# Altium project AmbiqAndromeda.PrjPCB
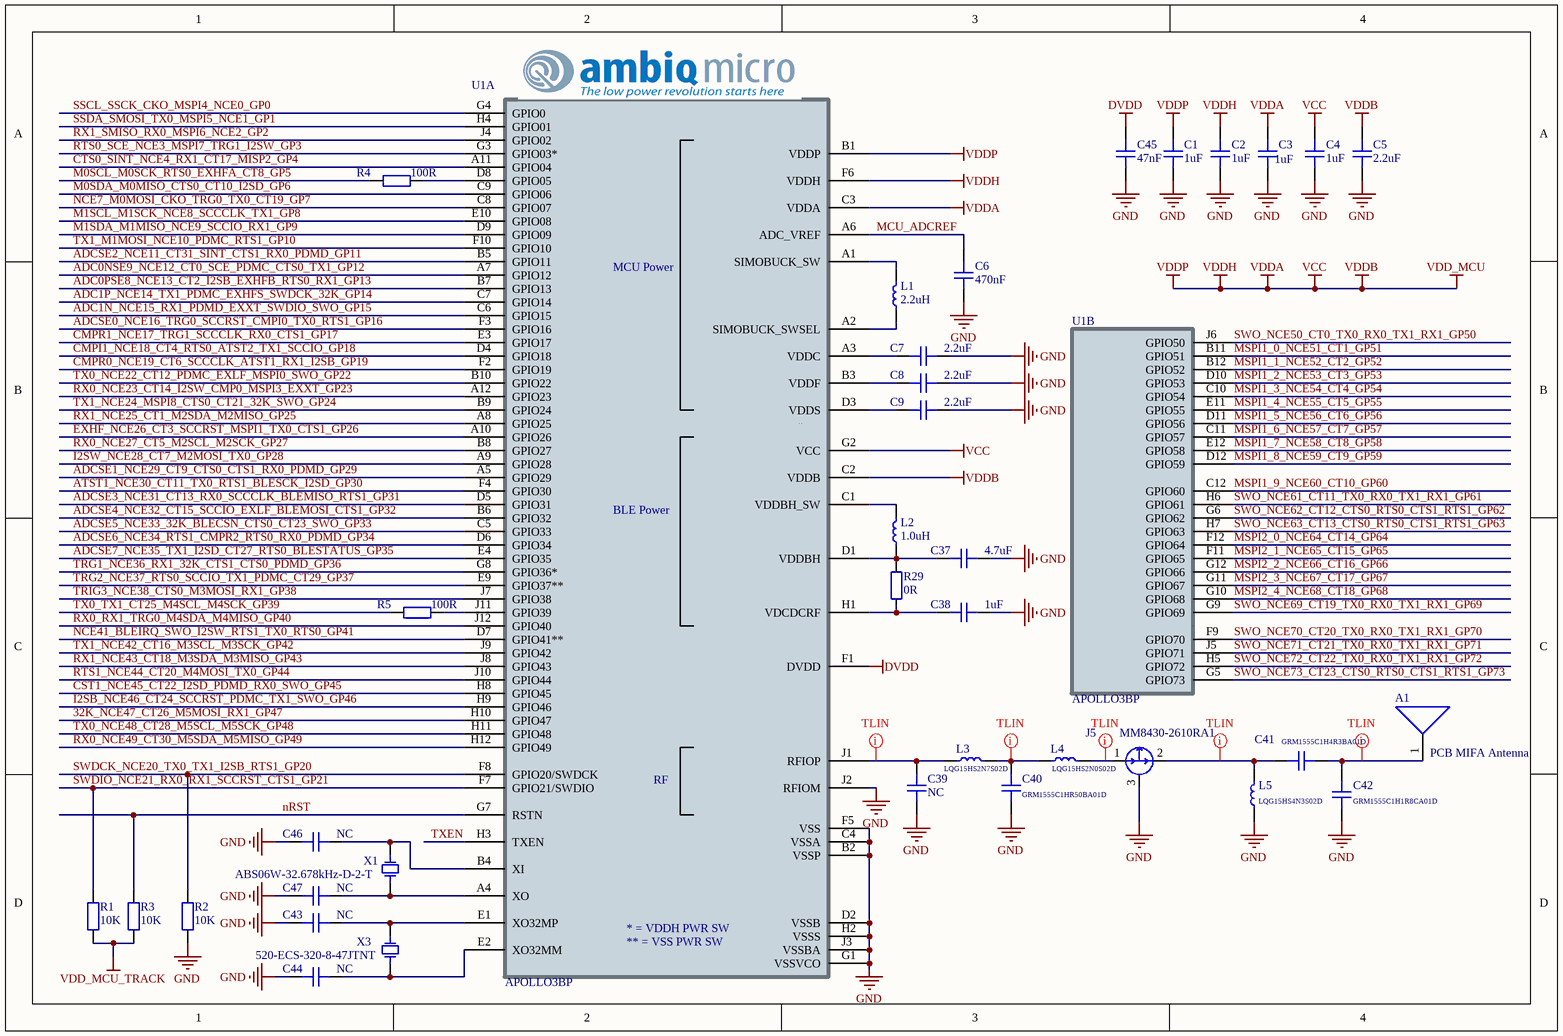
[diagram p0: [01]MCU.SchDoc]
10 sheets, 255 parts. Net scope: global (net labels, ports and power ports of the same name join across sheets).
Board file: AmbiqAndromeda.PcbDoc
Sheets:
  [01]MCU.SchDoc
  [02]Arduino Headers.SchDoc
  [03]Breakout Headers.SchDoc
  [04]Power Supplies.SchDoc
  [05]Power Supply Tracker.SchDoc
  [06]J-Link OB Debugger.SchDoc
  [07]User Interface.SchDoc
  [08]Debug Headers and Support.SchDoc
  [09]USBHub.SchDoc
  [10]USBSPIBridge.SchDoc

## Sheet [01]MCU.SchDoc
size A4; Organization: Altium Limited; Address1: L3, 12a Rodborough Rd; Address2: Frenchs Forest; Address3: NSW; Address4: Australia 2086

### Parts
A1  PCB MIFA Antenna  [MIFA_AMBIQ]  (net tie, no BOM)
C1  1uF  [CAPC0603L]
C2  1uF  [CAPC0603L]
C3  1uF  [CAPC0603L]
C4  1uF  [CAPC0603L]
C5  2.2uF  [CAPC0603L]
C6  470nF  [CAPC0603L]
C7  2.2uF  [CAPC0603L]
C8  2.2uF  [CAPC0603L]
C9  2.2uF  [CAPC0603L]
C37  4.7uF  [CAPC0603L]
C38  1uF  [CAPC0603L]
C39  NC  [CAPC1005L]
C40  GRM1555C1HR50BA01D  [CAPC1005L]
C41  GRM1555C1H4R3BA01D  [CAPC1005L]
C42  GRM1555C1H1R8CA01D  [CAPC1005L]
C43  NC  [CAPC0603L]
C44  NC  [CAPC0603L]
C45  47nF  [CAPC0603L]
C46  NC  [CAPC0603L]
C47  NC  [CAPC0603L]
J5  MM8430-2610RA1  [MM8430-2610RA1]
L1  2.2uH  [BRC2012]
L2  1.0uH  [DFE18SAN]
L3  LQG15HS2N7S02D  [INDC1005L]
L4  LQG15HS2N0S02D  [INDC1005L]
L5  LQG15HS4N3S02D  [INDC1005L]
R1  10K  [RESC1005L]
R2  10K  [RESC1005L]
R3  10K  [RESC1005L]
R4  100R  [RESC1005L]
R5  100R  [RESC1005L]
R29  0R  [RESC0603L]
U1  APOLLO3BP  [BGA104C40P12X9_530X430X80L]  (parts A,B of 2)
X1  ABS06W-32.678kHz-D-2-T  [ABS06W]
X3  520-ECS-320-8-47JTNT  [ECX-1247]

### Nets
DVDD: C45.2 U1.F1(DVDD)
GND: C1.1 C2.1 C3.1 C4.1 C5.1 C6.1 C7.1 C8.1 C9.1 C37.1 C38.1 C39.2 C40.2 C42.2 C43.2 C44.2 C45.1 C46.2 C47.2 J5.3 L5.1 R2.1 U1.B2(VSSP) U1.C4(VSSA) U1.D2(VSSB) U1.F5(VSS) U1.G1(VSSVCO) U1.H2(VSSS) U1.J2(RFIOM) U1.J3(VSSBA) X3.2(GND) X3.4(GND)
VDD_MCU: C1.2 C2.2 C3.2 C4.2 C5.2 U1.B1(VDDP) U1.C2(VDDB) U1.C3(VDDA) U1.F6(VDDH) U1.G2(VCC)  [also labelled VCC, VDDA, VDDB, VDDH, VDDP]
VDD_MCU_TRACK: R1.1 R3.1
32K_NCE47_CT26_M5MOSI_RX1_GP47: U1.H10(GPIO47)
ADC0NSE9_NCE12_CT0_SCE_PDMC_CTS0_TX1_GP12: U1.A7(GPIO12)
ADC0PSE8_NCE13_CT2_I2SB_EXHFB_RTS0_RX1_GP13: U1.B7(GPIO13)
ADC1N_NCE15_RX1_PDMD_EXXT_SWDIO_SWO_GP15: U1.C6(GPIO15)
ADC1P_NCE14_TX1_PDMC_EXHFS_SWDCK_32K_GP14: U1.C7(GPIO14)
ADCSE0_NCE16_TRG0_SCCRST_CMPI0_TX0_RTS1_GP16: U1.F3(GPIO16)
ADCSE1_NCE29_CT9_CTS0_CTS1_RX0_PDMD_GP29: U1.A5(GPIO29)
ADCSE2_NCE11_CT31_SINT_CTS1_RX0_PDMD_GP11: U1.B5(GPIO11)
ADCSE3_NCE31_CT13_RX0_SCCCLK_BLEMISO_RTS1_GP31: U1.D5(GPIO31)
ADCSE4_NCE32_CT15_SCCIO_EXLF_BLEMOSI_CTS1_GP32: U1.B6(GPIO32)
ADCSE5_NCE33_32K_BLECSN_CTS0_CT23_SWO_GP33: U1.C5(GPIO33)
ADCSE6_NCE34_RTS1_CMPR2_RTS0_RX0_PDMD_GP34: U1.D6(GPIO34)
ADCSE7_NCE35_TX1_I2SD_CT27_RTS0_BLESTATUS_GP35: U1.E4(GPIO35)
ATST1_NCE30_CT11_TX0_RTS1_BLESCK_I2SD_GP30: U1.F4(GPIO30)
CMPI1_NCE18_CT4_RTS0_ATST2_TX1_SCCIO_GP18: U1.D4(GPIO18)
CMPR0_NCE19_CT6_SCCCLK_ATST1_RX1_I2SB_GP19: U1.F2(GPIO19)
CMPR1_NCE17_TRG1_SCCCLK_RX0_CTS1_GP17: U1.E3(GPIO17)
CST1_NCE45_CT22_I2SD_PDMD_RX0_SWO_GP45: U1.H8(GPIO45)
CTS0_SINT_NCE4_RX1_CT17_MISP2_GP4: U1.A11(GPIO04)
EXHF_NCE26_CT3_SCCRST_MSPI1_TX0_CTS1_GP26: U1.A10(GPIO26)
I2SB_NCE46_CT24_SCCRST_PDMC_TX1_SWO_GP46: U1.H9(GPIO46)
I2SW_NCE28_CT7_M2MOSI_TX0_GP28: U1.A9(GPIO28)
M0SCL_M0SCK_RTS0_EXHFA_CT8_GP5: R4.1
M0SDA_M0MISO_CTS0_CT10_I2SD_GP6: U1.C9(GPIO06)
M1SCL_M1SCK_NCE8_SCCCLK_TX1_GP8: U1.E10(GPIO08)
M1SDA_M1MISO_NCE9_SCCIO_RX1_GP9: U1.D9(GPIO09)
MCU_ADCREF: C6.2 U1.A6(ADC_VREF)
MSPI1_0_NCE51_CT1_GP51: U1.B11(GPIO51)
MSPI1_1_NCE52_CT2_GP52: U1.B12(GPIO52)
MSPI1_2_NCE53_CT3_GP53: U1.D10(GPIO53)
MSPI1_3_NCE54_CT4_GP54: U1.C10(GPIO54)
MSPI1_4_NCE55_CT5_GP55: U1.E11(GPIO55)
MSPI1_5_NCE56_CT6_GP56: U1.D11(GPIO56)
MSPI1_6_NCE57_CT7_GP57: U1.C11(GPIO57)
MSPI1_7_NCE58_CT8_GP58: U1.E12(GPIO58)
MSPI1_8_NCE59_CT9_GP59: U1.D12(GPIO59)
MSPI1_9_NCE60_CT10_GP60: U1.C12(GPIO60)
MSPI2_0_NCE64_CT14_GP64: U1.F12(GPIO64)
MSPI2_1_NCE65_CT15_GP65: U1.F11(GPIO65)
MSPI2_2_NCE66_CT16_GP66: U1.G12(GPIO66)
MSPI2_3_NCE67_CT17_GP67: U1.G11(GPIO67)
MSPI2_4_NCE68_CT18_GP68: U1.G10(GPIO68)
NCE7_M0MOSI_CKO_TRG0_TX0_CT19_GP7: U1.C8(GPIO07)
NCE41_BLEIRQ_SWO_I2SW_RTS1_TX0_RTS0_GP41: U1.D7(GPIO41**)
nRST: R3.2 U1.G7(RSTN)  [project net AT_SWRST]
RTS0_SCE_NCE3_MSPI7_TRG1_I2SW_GP3: U1.G3(GPIO03*)
RTS1_NCE44_CT20_M4MOSI_TX0_GP44: U1.J10(GPIO44)
RX0_NCE23_CT14_I2SW_CMP0_MSPI3_EXXT_GP23: U1.A12(GPIO23)
RX0_NCE27_CT5_M2SCL_M2SCK_GP27: U1.B8(GPIO27)
RX0_NCE49_CT30_M5SDA_M5MISO_GP49: U1.H12(GPIO49)
RX0_RX1_TRG0_M4SDA_M4MISO_GP40: U1.J12(GPIO40)
RX1_NCE25_CT1_M2SDA_M2MISO_GP25: U1.A8(GPIO25)
RX1_NCE43_CT18_M3SDA_M3MISO_GP43: U1.J8(GPIO43)
RX1_SMISO_RX0_MSPI6_NCE2_GP2: U1.J4(GPIO02)
SSCL_SSCK_CKO_MSPI4_NCE0_GP0: U1.G4(GPIO0)
SSDA_SMOSI_TX0_MSPI5_NCE1_GP1: U1.H4(GPIO01)
SWDCK_NCE20_TX0_TX1_I2SB_RTS1_GP20: R2.2 U1.F8(GPIO20/SWDCK)
SWDIO_NCE21_RX0_RX1_SCCRST_CTS1_GP21: R1.2 U1.F7(GPIO21/SWDIO)
SWO_NCE50_CT0_TX0_RX0_TX1_RX1_GP50: U1.J6(GPIO50)
SWO_NCE61_CT11_TX0_RX0_TX1_RX1_GP61: U1.H6(GPIO61)
SWO_NCE62_CT12_CTS0_RTS0_CTS1_RTS1_GP62: U1.G6(GPIO62)
SWO_NCE63_CT13_CTS0_RTS0_CTS1_RTS1_GP63: U1.H7(GPIO63)
SWO_NCE69_CT19_TX0_RX0_TX1_RX1_GP69: U1.G9(GPIO69)
SWO_NCE70_CT20_TX0_RX0_TX1_RX1_GP70: U1.F9(GPIO70)
SWO_NCE71_CT21_TX0_RX0_TX1_RX1_GP71: U1.J5(GPIO71)
SWO_NCE72_CT22_TX0_RX0_TX1_RX1_GP72: U1.H5(GPIO72)
SWO_NCE73_CT23_CTS0_RTS0_CTS1_RTS1_GP73: U1.G5(GPIO73)
TRG1_NCE36_RX1_32K_CTS1_CTS0_PDMD_GP36: U1.G8(GPIO36*)
TRG2_NCE37_RTS0_SCCIO_TX1_PDMC_CT29_GP37: U1.E9(GPIO37**)
TRIG3_NCE38_CTS0_M3MOSI_RX1_GP38: U1.J7(GPIO38)
TX0_NCE22_CT12_PDMC_EXLF_MSPI0_SWO_GP22: U1.B10(GPIO22)
TX0_NCE48_CT28_M5SCL_M5SCK_GP48: U1.H11(GPIO48)
TX0_TX1_CT25_M4SCL_M4SCK_GP39: R5.1
TX1_M1MOSI_NCE10_PDMC_RTS1_GP10: U1.F10(GPIO10)
TX1_NCE24_MSPI8_CTS0_CT21_32K_SWO_GP24: U1.B9(GPIO24)
TX1_NCE42_CT16_M3SCL_M3SCK_GP42: U1.J9(GPIO42)
TXEN: U1.H3(TXEN)
NetA1_1: A1.1 C41.2 C42.1
NetC7_2: C7.2 U1.A3(VDDC)
NetC8_2: C8.2 U1.B3(VDDF)
NetC9_2: C9.2 U1.D3(VDDS)
NetC37_2: C37.2 L2.1 R29.2 U1.D1(VDDBH)
NetC38_2: C38.2 R29.1 U1.H1(VDCDCRF)
NetC39_1: C39.1 L3.1 U1.J1(RFIOP)
NetC40_1: C40.1 L3.2 L4.1
NetC41_1: C41.1 J5.2 L5.2
NetC43_1: C43.1 U1.E1(XO32MP) X3.3
NetC44_1: C44.1 U1.E2(XO32MM) X3.1
NetC46_1: C46.1 U1.B4(XI) X1.2
NetC47_1: C47.1 U1.A4(XO) X1.1
NetJ5_1: J5.1 L4.2
NetL1_1: L1.1 U1.A2(SIMOBUCK_SWSEL)
NetL1_2: L1.2 U1.A1(SIMOBUCK_SW)
NetL2_2: L2.2 U1.C1(VDDBH_SW)
NetR4_2: R4.2 U1.D8(GPIO05)
NetR5_2: R5.2 U1.J11(GPIO39)

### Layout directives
net class TLIN50: NetA1_1, NetC39_1, NetC40_1, NetC41_1, NetJ5_1

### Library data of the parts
A1 = ANT_PCB: 2.4G Printed Antenna
C1-C9 C37-C47 = CAP_CHP: Surface Mount Unpolarized Capacitor
J5 = MM8430-2610RA1: SWD Connector Receptacle, Female Socket 50 Ohm Surface Mount Solder
L1 = IND_PWR: DFE201610E-2R2M=P2
L2 = IND_PWR: DFE18SAN1R0MG0L
L3-L5 = IND_CHP: Chip Inductor
R1-R5 R29 = RES_CHP: Surface Mount Resistor
U1 = APOLLO3BP-BGA: APOLLO3 Blue Plus; Manufacturer: Ambiq Micro
X1 = ABS06W-32.678kHz-D-2-T: 32.768KHZ IoT OPTIMIZED SMD CRYSTA
X3 = ECX-1247: XTAL 32MHZ 8pF 20ppm  1.6mm x 1.2mm x 0.35mm SMT

## Sheet [02]Arduino Headers.SchDoc
size A4; Organization: Altium Limited; Address1: L3, 12a Rodborough Rd; Address2: Frenchs Forest; Address3: NSW; Address4: Australia 2086
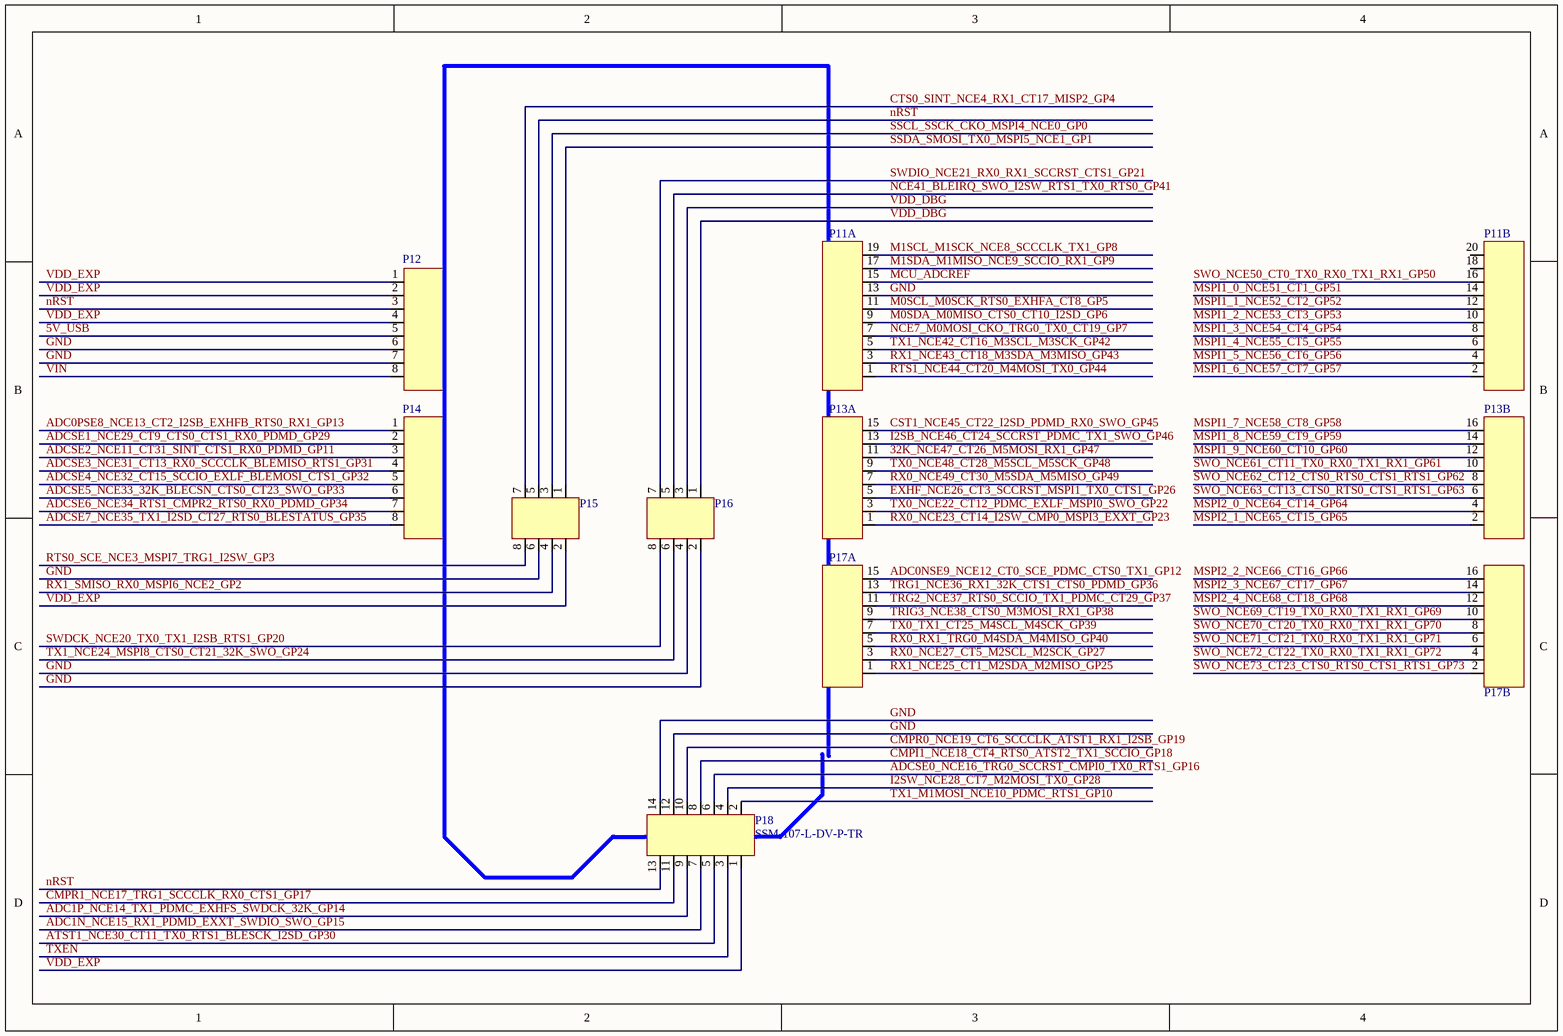
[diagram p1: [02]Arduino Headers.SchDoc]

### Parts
P11  SSM-110-L-DV-P-TR  [SSM-110-L-DV-TR]  (value not drawn)  (parts A,B of 2)
P12  SSM-108-L-SV-P-TR  [SSM-108-L-SV-TR]  (value not drawn)
P13  SSM-108-L-DV-P-TR  [SSM-108-L-DV-TR]  (value not drawn)  (parts A,B of 2)
P14  SSM-108-L-SV-P-TR  [SSM-108-L-SV-TR]  (value not drawn)
P15  TSM-104-04-F-DV-P-TR  [TSM-104-04-F-DV-TR]  (value not drawn)
P16  TSM-104-04-F-DV-P-TR  [TSM-104-04-F-DV-TR]  (value not drawn)
P17  SSM-108-L-DV-P-TR  [SSM-108-L-DV-TR]  (value not drawn)  (parts A,B of 2)
P18  SSM-107-L-DV-P-TR  [SSM-107-L-DV-TR]

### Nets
5V_USB: P12.5
GND: P11.13 P12.6 P12.7 P15.6 P16.2 P16.4 P18.12 P18.14
VDD_DBG: P16.1 P16.3
32K_NCE47_CT26_M5MOSI_RX1_GP47: P13.11
ADC0NSE9_NCE12_CT0_SCE_PDMC_CTS0_TX1_GP12: P17.15
ADC0PSE8_NCE13_CT2_I2SB_EXHFB_RTS0_RX1_GP13: P14.1
ADC1N_NCE15_RX1_PDMD_EXXT_SWDIO_SWO_GP15: P18.7
ADC1P_NCE14_TX1_PDMC_EXHFS_SWDCK_32K_GP14: P18.9
ADCSE0_NCE16_TRG0_SCCRST_CMPI0_TX0_RTS1_GP16: P18.6
ADCSE1_NCE29_CT9_CTS0_CTS1_RX0_PDMD_GP29: P14.2
ADCSE2_NCE11_CT31_SINT_CTS1_RX0_PDMD_GP11: P14.3
ADCSE3_NCE31_CT13_RX0_SCCCLK_BLEMISO_RTS1_GP31: P14.4
ADCSE4_NCE32_CT15_SCCIO_EXLF_BLEMOSI_CTS1_GP32: P14.5
ADCSE5_NCE33_32K_BLECSN_CTS0_CT23_SWO_GP33: P14.6
ADCSE6_NCE34_RTS1_CMPR2_RTS0_RX0_PDMD_GP34: P14.7
ADCSE7_NCE35_TX1_I2SD_CT27_RTS0_BLESTATUS_GP35: P14.8
ATST1_NCE30_CT11_TX0_RTS1_BLESCK_I2SD_GP30: P18.5
CMPI1_NCE18_CT4_RTS0_ATST2_TX1_SCCIO_GP18: P18.8
CMPR0_NCE19_CT6_SCCCLK_ATST1_RX1_I2SB_GP19: P18.10
CMPR1_NCE17_TRG1_SCCCLK_RX0_CTS1_GP17: P18.11
CST1_NCE45_CT22_I2SD_PDMD_RX0_SWO_GP45: P13.15
CTS0_SINT_NCE4_RX1_CT17_MISP2_GP4: P15.7
EXHF_NCE26_CT3_SCCRST_MSPI1_TX0_CTS1_GP26: P13.5
I2SB_NCE46_CT24_SCCRST_PDMC_TX1_SWO_GP46: P13.13
I2SW_NCE28_CT7_M2MOSI_TX0_GP28: P18.4
M0SCL_M0SCK_RTS0_EXHFA_CT8_GP5: P11.11
M0SDA_M0MISO_CTS0_CT10_I2SD_GP6: P11.9
M1SCL_M1SCK_NCE8_SCCCLK_TX1_GP8: P11.19
M1SDA_M1MISO_NCE9_SCCIO_RX1_GP9: P11.17
MCU_ADCREF: P11.15
MSPI1_0_NCE51_CT1_GP51: P11.14
MSPI1_1_NCE52_CT2_GP52: P11.12
MSPI1_2_NCE53_CT3_GP53: P11.10
MSPI1_3_NCE54_CT4_GP54: P11.8
MSPI1_4_NCE55_CT5_GP55: P11.6
MSPI1_5_NCE56_CT6_GP56: P11.4
MSPI1_6_NCE57_CT7_GP57: P11.2
MSPI1_7_NCE58_CT8_GP58: P13.16
MSPI1_8_NCE59_CT9_GP59: P13.14
MSPI1_9_NCE60_CT10_GP60: P13.12
MSPI2_0_NCE64_CT14_GP64: P13.4
MSPI2_1_NCE65_CT15_GP65: P13.2
MSPI2_2_NCE66_CT16_GP66: P17.16
MSPI2_3_NCE67_CT17_GP67: P17.14
MSPI2_4_NCE68_CT18_GP68: P17.12
NCE7_M0MOSI_CKO_TRG0_TX0_CT19_GP7: P11.7
NCE41_BLEIRQ_SWO_I2SW_RTS1_TX0_RTS0_GP41: P16.5
nRST: P12.3 P15.5 P18.13  [project net AT_SWRST]
RTS0_SCE_NCE3_MSPI7_TRG1_I2SW_GP3: P15.8
RTS1_NCE44_CT20_M4MOSI_TX0_GP44: P11.1
RX0_NCE23_CT14_I2SW_CMP0_MSPI3_EXXT_GP23: P13.1
RX0_NCE27_CT5_M2SCL_M2SCK_GP27: P17.3
RX0_NCE49_CT30_M5SDA_M5MISO_GP49: P13.7
RX0_RX1_TRG0_M4SDA_M4MISO_GP40: P17.5
RX1_NCE25_CT1_M2SDA_M2MISO_GP25: P17.1
RX1_NCE43_CT18_M3SDA_M3MISO_GP43: P11.3
RX1_SMISO_RX0_MSPI6_NCE2_GP2: P15.4
SSCL_SSCK_CKO_MSPI4_NCE0_GP0: P15.3
SSDA_SMOSI_TX0_MSPI5_NCE1_GP1: P15.1
SWDCK_NCE20_TX0_TX1_I2SB_RTS1_GP20: P16.8
SWDIO_NCE21_RX0_RX1_SCCRST_CTS1_GP21: P16.7
SWO_NCE50_CT0_TX0_RX0_TX1_RX1_GP50: P11.16
SWO_NCE61_CT11_TX0_RX0_TX1_RX1_GP61: P13.10
SWO_NCE62_CT12_CTS0_RTS0_CTS1_RTS1_GP62: P13.8
SWO_NCE63_CT13_CTS0_RTS0_CTS1_RTS1_GP63: P13.6
SWO_NCE69_CT19_TX0_RX0_TX1_RX1_GP69: P17.10
SWO_NCE70_CT20_TX0_RX0_TX1_RX1_GP70: P17.8
SWO_NCE71_CT21_TX0_RX0_TX1_RX1_GP71: P17.6
SWO_NCE72_CT22_TX0_RX0_TX1_RX1_GP72: P17.4
SWO_NCE73_CT23_CTS0_RTS0_CTS1_RTS1_GP73: P17.2
TRG1_NCE36_RX1_32K_CTS1_CTS0_PDMD_GP36: P17.13
TRG2_NCE37_RTS0_SCCIO_TX1_PDMC_CT29_GP37: P17.11
TRIG3_NCE38_CTS0_M3MOSI_RX1_GP38: P17.9
TX0_NCE22_CT12_PDMC_EXLF_MSPI0_SWO_GP22: P13.3
TX0_NCE48_CT28_M5SCL_M5SCK_GP48: P13.9
TX0_TX1_CT25_M4SCL_M4SCK_GP39: P17.7
TX1_M1MOSI_NCE10_PDMC_RTS1_GP10: P18.2
TX1_NCE24_MSPI8_CTS0_CT21_32K_SWO_GP24: P16.6
TX1_NCE42_CT16_M3SCL_M3SCK_GP42: P11.5
TXEN: P18.3
VDD_EXP: P12.1 P12.2 P12.4 P15.2 P18.1
VIN: P12.8

Not connected (* = marked no-connect by the designer): P11 18 20

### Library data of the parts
P11 = SSM-110-L-DV-P-TR_2: 20 Position Receptacle, Pass Through Connector 2.54mm Gold SMD
P12 P14 = SSM-108-L-SV-P-TR: 8 Position Receptacle, Pass Through Connector 2.54mm Gold SMD
P13 P17 = SSM-108-L-DV-P-TR_2: 16 Position Receptacle, Pass Through Connector 2.54mm Gold SMD
P15 P16 = TSM-104-04-F-DV-P-TR: 8 Positions Header, 2 Row,Gold, Unshrouded Connector 2.54mm SMD
P18 = SSM-107-L-DV-P-TR: 14 Positions Socket Strip, Double Row Vertical 2,54mm SMD

## Sheet [03]Breakout Headers.SchDoc
size A4; Organization: Altium Limited; Address1: L3, 12a Rodborough Rd; Address2: Frenchs Forest; Address3: NSW; Address4: Australia 2086
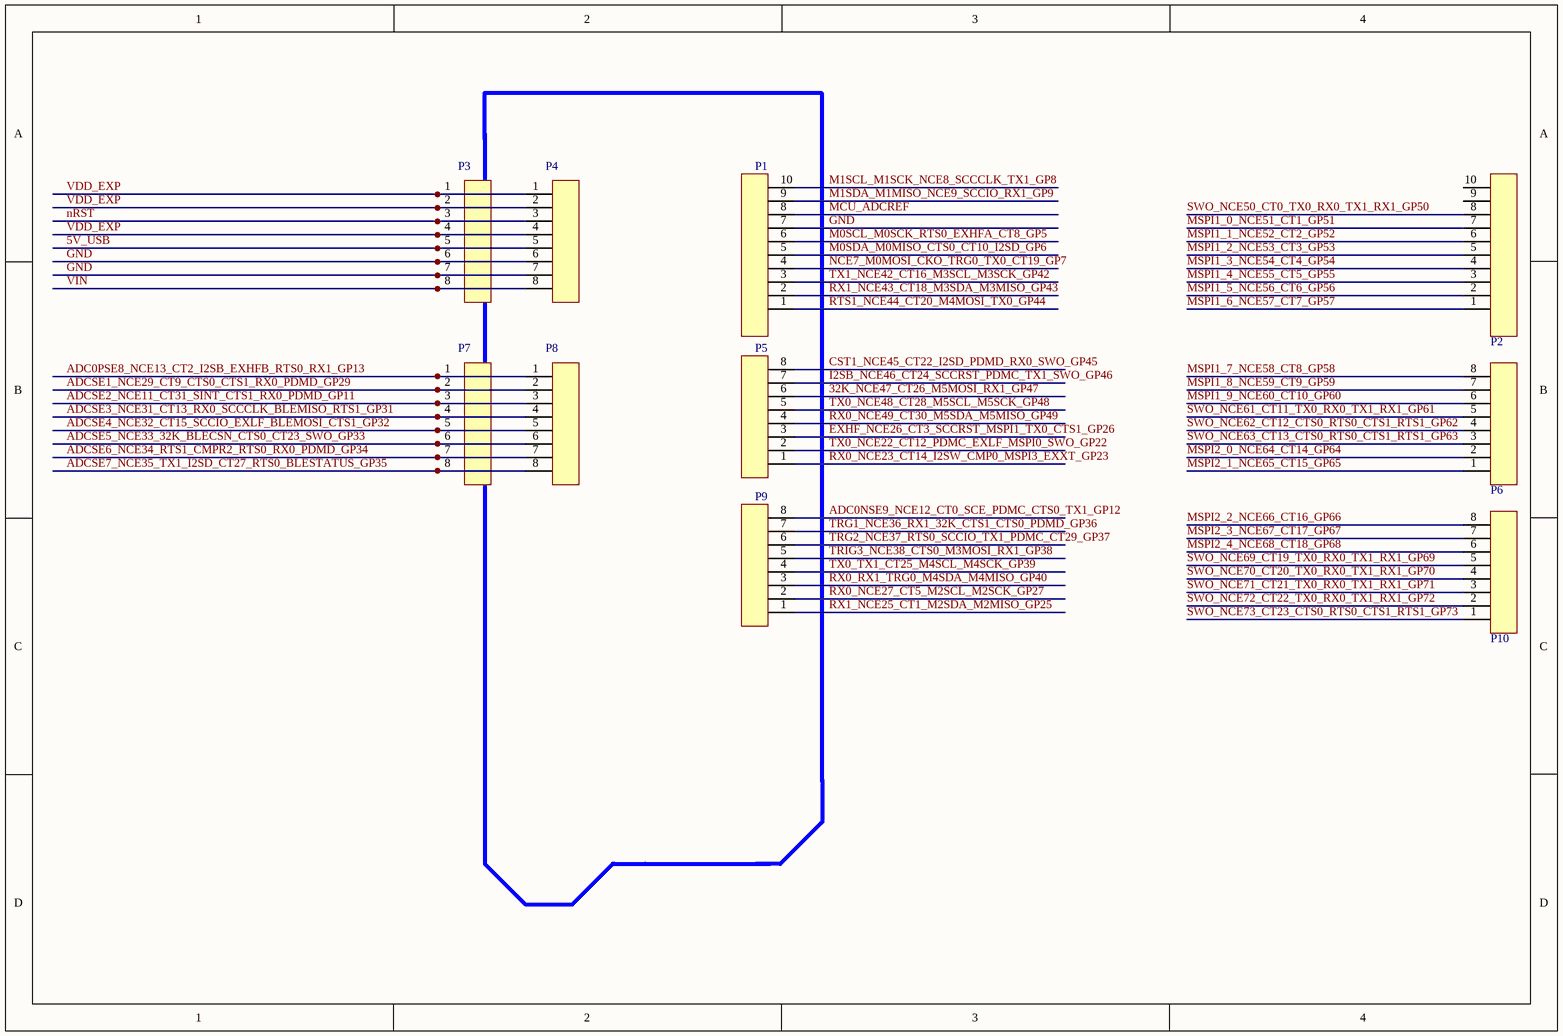
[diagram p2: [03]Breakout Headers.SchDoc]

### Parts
P1  Header 1X10  [HEADER1X10]  (value not drawn)  (no BOM)
P2  Header 1X10  [HEADER1X10]  (value not drawn)  (no BOM)
P3  Header 1X8  [HEADER1X8]  (value not drawn)  (no BOM)
P4  Header 1X8  [HEADER1X8]  (value not drawn)  (no BOM)
P5  Header 1X8  [HEADER1X8]  (value not drawn)  (no BOM)
P6  Header 1X8  [HEADER1X8]  (value not drawn)  (no BOM)
P7  Header 1X8  [HEADER1X8]  (value not drawn)  (no BOM)
P8  Header 1X8  [HEADER1X8]  (value not drawn)  (no BOM)
P9  Header 1X8  [HEADER1X8]  (value not drawn)  (no BOM)
P10  Header 1X8  [HEADER1X8]  (value not drawn)  (no BOM)

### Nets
5V_USB: P3.5 P4.5
GND: P1.7 P3.6 P3.7 P4.6 P4.7
32K_NCE47_CT26_M5MOSI_RX1_GP47: P5.6
ADC0NSE9_NCE12_CT0_SCE_PDMC_CTS0_TX1_GP12: P9.8
ADC0PSE8_NCE13_CT2_I2SB_EXHFB_RTS0_RX1_GP13: P7.1 P8.1
ADCSE1_NCE29_CT9_CTS0_CTS1_RX0_PDMD_GP29: P7.2 P8.2
ADCSE2_NCE11_CT31_SINT_CTS1_RX0_PDMD_GP11: P7.3 P8.3
ADCSE3_NCE31_CT13_RX0_SCCCLK_BLEMISO_RTS1_GP31: P7.4 P8.4
ADCSE4_NCE32_CT15_SCCIO_EXLF_BLEMOSI_CTS1_GP32: P7.5 P8.5
ADCSE5_NCE33_32K_BLECSN_CTS0_CT23_SWO_GP33: P7.6 P8.6
ADCSE6_NCE34_RTS1_CMPR2_RTS0_RX0_PDMD_GP34: P7.7 P8.7
ADCSE7_NCE35_TX1_I2SD_CT27_RTS0_BLESTATUS_GP35: P7.8 P8.8
CST1_NCE45_CT22_I2SD_PDMD_RX0_SWO_GP45: P5.8
EXHF_NCE26_CT3_SCCRST_MSPI1_TX0_CTS1_GP26: P5.3
I2SB_NCE46_CT24_SCCRST_PDMC_TX1_SWO_GP46: P5.7
M0SCL_M0SCK_RTS0_EXHFA_CT8_GP5: P1.6
M0SDA_M0MISO_CTS0_CT10_I2SD_GP6: P1.5
M1SCL_M1SCK_NCE8_SCCCLK_TX1_GP8: P1.10
M1SDA_M1MISO_NCE9_SCCIO_RX1_GP9: P1.9
MCU_ADCREF: P1.8
MSPI1_0_NCE51_CT1_GP51: P2.7
MSPI1_1_NCE52_CT2_GP52: P2.6
MSPI1_2_NCE53_CT3_GP53: P2.5
MSPI1_3_NCE54_CT4_GP54: P2.4
MSPI1_4_NCE55_CT5_GP55: P2.3
MSPI1_5_NCE56_CT6_GP56: P2.2
MSPI1_6_NCE57_CT7_GP57: P2.1
MSPI1_7_NCE58_CT8_GP58: P6.8
MSPI1_8_NCE59_CT9_GP59: P6.7
MSPI1_9_NCE60_CT10_GP60: P6.6
MSPI2_0_NCE64_CT14_GP64: P6.2
MSPI2_1_NCE65_CT15_GP65: P6.1
MSPI2_2_NCE66_CT16_GP66: P10.8
MSPI2_3_NCE67_CT17_GP67: P10.7
MSPI2_4_NCE68_CT18_GP68: P10.6
NCE7_M0MOSI_CKO_TRG0_TX0_CT19_GP7: P1.4
nRST: P3.3 P4.3  [project net AT_SWRST]
RTS1_NCE44_CT20_M4MOSI_TX0_GP44: P1.1
RX0_NCE23_CT14_I2SW_CMP0_MSPI3_EXXT_GP23: P5.1
RX0_NCE27_CT5_M2SCL_M2SCK_GP27: P9.2
RX0_NCE49_CT30_M5SDA_M5MISO_GP49: P5.4
RX0_RX1_TRG0_M4SDA_M4MISO_GP40: P9.3
RX1_NCE25_CT1_M2SDA_M2MISO_GP25: P9.1
RX1_NCE43_CT18_M3SDA_M3MISO_GP43: P1.2
SWO_NCE50_CT0_TX0_RX0_TX1_RX1_GP50: P2.8
SWO_NCE61_CT11_TX0_RX0_TX1_RX1_GP61: P6.5
SWO_NCE62_CT12_CTS0_RTS0_CTS1_RTS1_GP62: P6.4
SWO_NCE63_CT13_CTS0_RTS0_CTS1_RTS1_GP63: P6.3
SWO_NCE69_CT19_TX0_RX0_TX1_RX1_GP69: P10.5
SWO_NCE70_CT20_TX0_RX0_TX1_RX1_GP70: P10.4
SWO_NCE71_CT21_TX0_RX0_TX1_RX1_GP71: P10.3
SWO_NCE72_CT22_TX0_RX0_TX1_RX1_GP72: P10.2
SWO_NCE73_CT23_CTS0_RTS0_CTS1_RTS1_GP73: P10.1
TRG1_NCE36_RX1_32K_CTS1_CTS0_PDMD_GP36: P9.7
TRG2_NCE37_RTS0_SCCIO_TX1_PDMC_CT29_GP37: P9.6
TRIG3_NCE38_CTS0_M3MOSI_RX1_GP38: P9.5
TX0_NCE22_CT12_PDMC_EXLF_MSPI0_SWO_GP22: P5.2
TX0_NCE48_CT28_M5SCL_M5SCK_GP48: P5.5
TX0_TX1_CT25_M4SCL_M4SCK_GP39: P9.4
TX1_NCE42_CT16_M3SCL_M3SCK_GP42: P1.3
VDD_EXP: P3.1 P3.2 P3.4 P4.1 P4.2 P4.4
VIN: P3.8 P4.8

Not connected (* = marked no-connect by the designer): P2 9 10

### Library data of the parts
P1 P2 = HDR1X10
P3-P10 = HDR1X8

## Sheet [04]Power Supplies.SchDoc
size A4; Organization: Altium Limited; Address1: L3, 12a Rodborough Rd; Address2: Frenchs Forest; Address3: NSW; Address4: Australia 2086
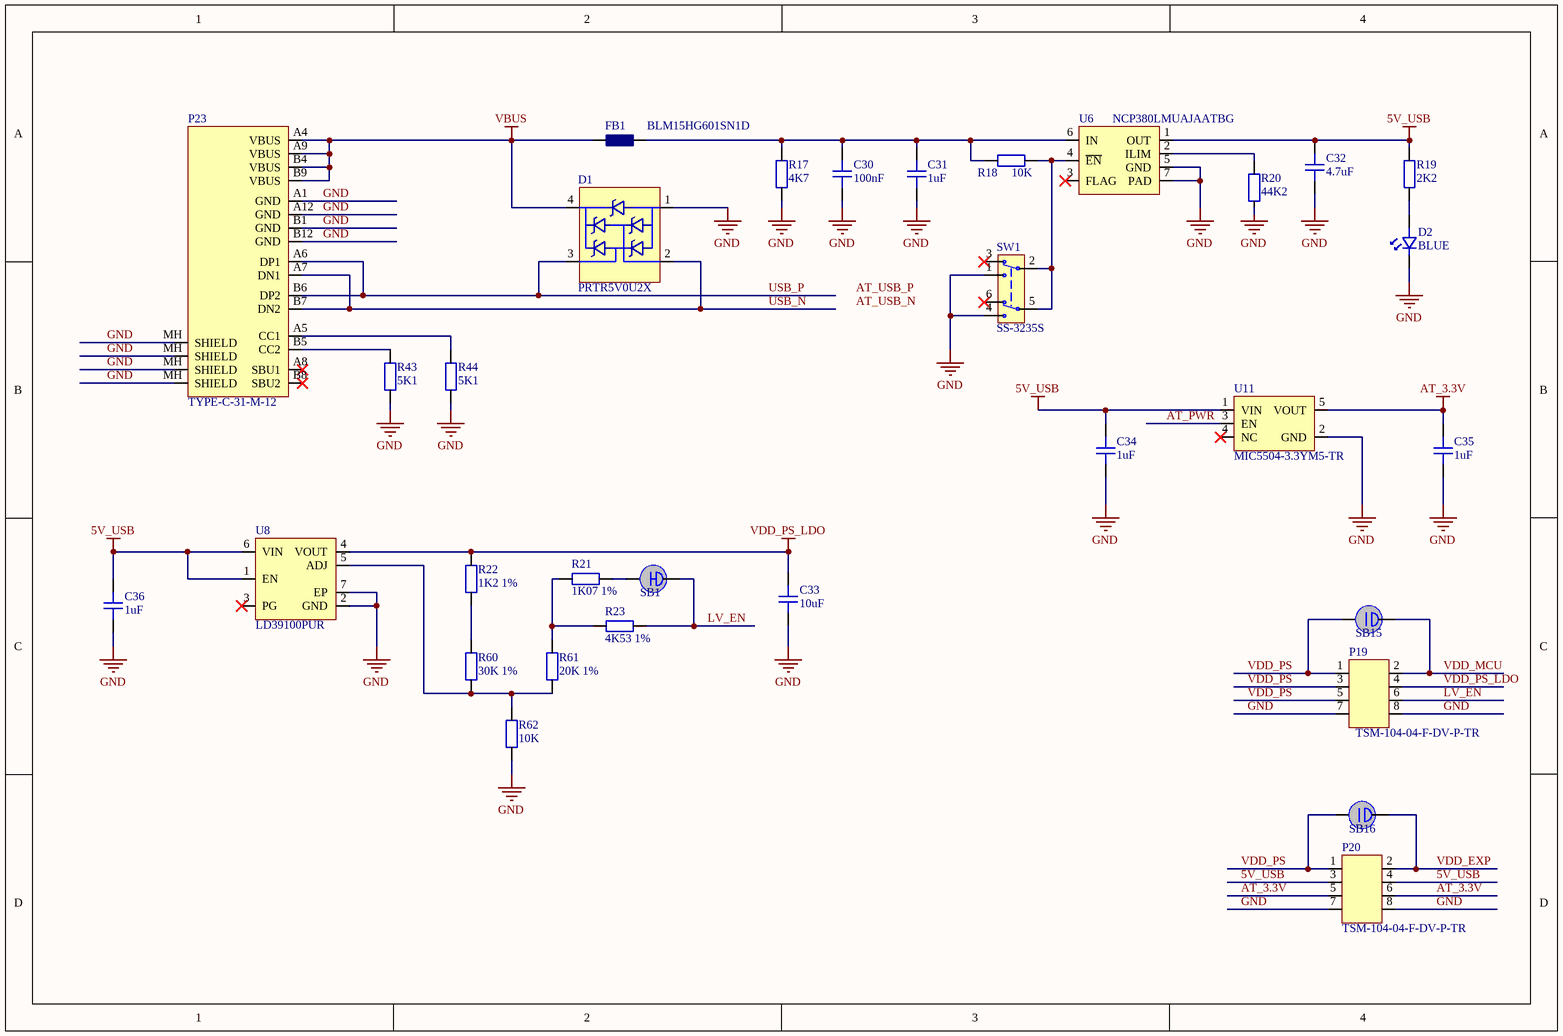
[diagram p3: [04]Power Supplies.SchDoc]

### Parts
C30  100nF  [CAPC1005L]
C31  1uF  [CAPC1005L]
C32  4.7uF  [CAPC1005L]
C33  10uF  [CAPC1608N]
C34  1uF  [CAPC1005L]
C35  1uF  [CAPC1005L]
C36  1uF  [CAPC1005L]
D1  PRTR5V0U2X  [SOT143L]
D2  BLUE  [LEDC1608L]
FB1  BLM15HG601SN1D  [FBDC1005L]
P19  TSM-104-04-F-DV-P-TR  [TSM-104-04-F-DV-TR]
P20  TSM-104-04-F-DV-P-TR  [TSM-104-04-F-DV-TR]
P23  TYPE-C-31-M-12  [TYPE-C-31-M-12]
R17  4K7  [RESC1005L]
R18  10K  [RESC1005L]
R19  2K2  [RESC1005L]
R20  44K2  [RESC1005L]
R21  1K07 1%  [RESC1005L]
R22  1K2 1%  [RESC1005L]
R23  4K53 1%  [RESC1005L]
R43  5K1  [RESC1005L]
R44  5K1  [RESC1005L]
R60  30K 1%  [RESC1005L]
R61  20K 1%  [RESC1005L]
R62  10K  [RESC1005L]
SB1  SBS  [SBS]  (value not drawn)  (net tie, no BOM)
SB15  SBO  [SBO]  (value not drawn)  (no BOM)
SB16  SBO  [SBO]  (value not drawn)  (no BOM)
SW1  SS-3235S  [JS202011SCQN]
U6  NCP380LMUAJAATBG  [UDFN-6]
U8  LD39100PUR  [DFN6]
U11  MIC5504-3.3YM5-TR  [SOT23-5_L]

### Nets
5V_USB: C32.2 C34.2 C36.2 P20.3 P20.4 R19.1 U6.1(OUT) U8.1(EN) U8.6(VIN) U11.1(VIN)
AT_3.3V: C35.2 P20.5 P20.6 U11.5(VOUT)
GND: C30.1 C31.1 C32.1 C33.1 C34.1 C35.1 C36.1 D1.1 D2.1 P19.7 P19.8 P20.7 P20.8 P23.A1(GND) P23.A12(GND) P23.B1(GND) P23.B12(GND) P23.MH(SHIELD) R17.1 R20.2 R43.1 R44.1 R62.1 SW1.1 SW1.4 U6.5(GND) U6.7(PAD) U8.2(GND) U8.7(EP) U11.2(GND)
VBUS: D1.4 FB1.1 P23.A4(VBUS) P23.A9(VBUS) P23.B4(VBUS) P23.B9(VBUS)
VDD_MCU: P19.2 SB15.2
VDD_PS_LDO: C33.2 P19.4 R22.2 U8.4(VOUT)
AT_PWR: U11.3(EN)
LV_EN: P19.6 R23.1 SB1.2
USB_N: D1.2 P23.A7(DN1) P23.B7(DN2)
USB_P: D1.3 P23.A6(DP1) P23.B6(DP2)
VDD_EXP: P20.2 SB16.2
VDD_PS: P19.1 P19.3 P19.5 P20.1 SB15.1 SB16.1
NetC30_2: C30.2 C31.2 FB1.2 R17.2 R18.2 U6.6(IN)
NetD2_2: D2.2 R19.2
NetP23_A5: P23.A5(CC1) R44.2
NetP23_B5: P23.B5(CC2) R43.2
NetR18_1: R18.1 SW1.2 SW1.5 U6.4(~{EN})
NetR20_1: R20.1 U6.2(ILIM)
NetR21_1: R21.1 SB1.1
NetR21_2: R21.2 R23.2 R61.2
NetR22_1: R22.1 R60.2
NetR60_1: R60.1 R61.1 R62.2 U8.5(ADJ)

Not connected (* = marked no-connect by the designer): P23 A8(SBU1)* B8(SBU2)*; SW1 3* 6*; U6 3(FLAG)*; U8 3(PG)*; U11 4(NC)*

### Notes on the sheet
- Labels drawn without touching a wire or pin: AT_USB_N, AT_USB_P

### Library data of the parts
C30-C36 = CAP_CHP: Surface Mount Unpolarized Capacitor
D1 = PRTR5V0U2X: Ultra low capacitance double rail-to-rail ESD protection diode
D2 = LED_SMD: Surface Mount LED
FB1 = FBD_CHP: Surface Mount Ferrite Bead
P19 P20 = TSM-104-04-F-DV-P-TR: as P15 on sheet [02]Arduino Headers
P23 = TYPE-C-31-M-12: USB Type-C Connector
R17-R23 R43 R44 R60-R62 = RES_CHP: Surface Mount Resistor
SB1 = SBS: Short-circuit soldering bridge
SB15 SB16 = SBO: Open-circuit soldering bridge
SW1 = SS-3235S: Slide Switch DPDT Surface Mount 9x3.5x3.5  Pitch=2.5mm
U6 = NCP380: IC CURRENT LIMIT SWITCH UDFN6
U8 = LD39100PUR: Voltage Regulator, 1A, Low Quiescent Current  ,DFN6 Tape&Reel
U11 = MIC5504-3.3YM5-TR: Linear Voltage Regulator Positive Fixed 1 Output 3.3V 300mA SOT-23-5

## Sheet [05]Power Supply Tracker.SchDoc
size A4; Organization: Altium Limited; Address1: L3, 12a Rodborough Rd; Address2: Frenchs Forest; Address3: NSW; Address4: Australia 2086
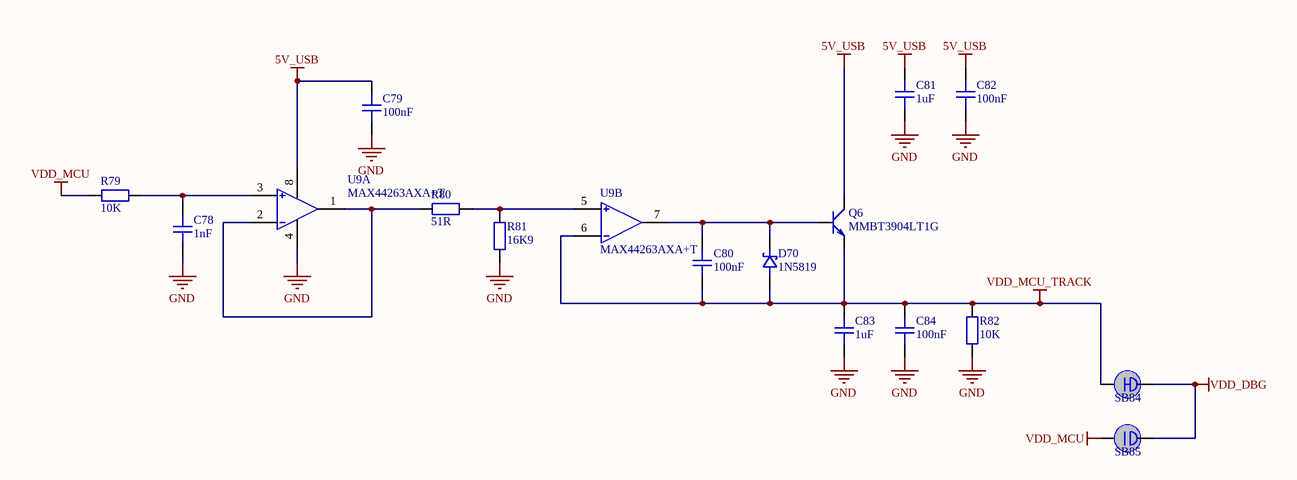
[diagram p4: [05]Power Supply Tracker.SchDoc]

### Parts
C78  1nF  [CAPC1005L]
C79  100nF  [CAPC1005L]
C80  100nF  [CAPC1005L]
C81  1uF  [CAPC1005L]
C82  100nF  [CAPC1005L]
C83  1uF  [CAPC1005L]
C84  100nF  [CAPC1005L]
D70  1N5819  [SOD2512X100L]
Q6  MMBT3904LT1G  [SOT23-3N]
R79  10K  [RESC1005L]
R80  51R  [RESC1005L]
R81  16K9  [RESC1005L]
R82  10K  [RESC1005L]
SB84  SBS  [SBS]  (value not drawn)  (net tie, no BOM)
SB85  SBO  [SBO]  (value not drawn)  (no BOM)
U9  MAX44263AXA+T  [SC-70-8]  (parts A,B of 2)

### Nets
5V_USB: C79.2 C81.2 C82.2 Q6.3 U9.8
GND: C78.1 C79.1 C81.1 C82.1 C83.1 C84.1 R81.1 R82.1 U9.4
VDD_DBG: SB84.2 SB85.2
VDD_MCU: R79.1 SB85.1
VDD_MCU_TRACK: C80.1 C83.2 C84.2 D70.2 Q6.2 R82.2 SB84.1 U9.6(VIN-)
NetC78_2: C78.2 R79.2 U9.3(VIN+)
NetC80_2: C80.2 D70.1 Q6.1 U9.7(OUT)
NetR80_1: R80.1 U9.1(OUT) U9.2(VIN-)
NetR80_2: R80.2 R81.2 U9.5(VIN+)

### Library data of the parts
C78-C84 = CAP_CHP: Surface Mount Unpolarized Capacitor
D70 = SKT_SMD: Surface Mount Diode
Q6 = TRAN_NPN: Surface Mount NPN Transistor
R79-R82 = RES_CHP: Surface Mount Resistor
SB84 = SBS: Short-circuit soldering bridge
SB85 = SBO: Open-circuit soldering bridge
U9 = MAX44263: General Purpose Amplifier 2 Circuit Rail-to-Rail

## Sheet [06]J-Link OB Debugger.SchDoc
size A4; Organization: Altium Limited; Address1: L3, 12a Rodborough Rd; Address2: Frenchs Forest; Address3: NSW; Address4: Australia 2086
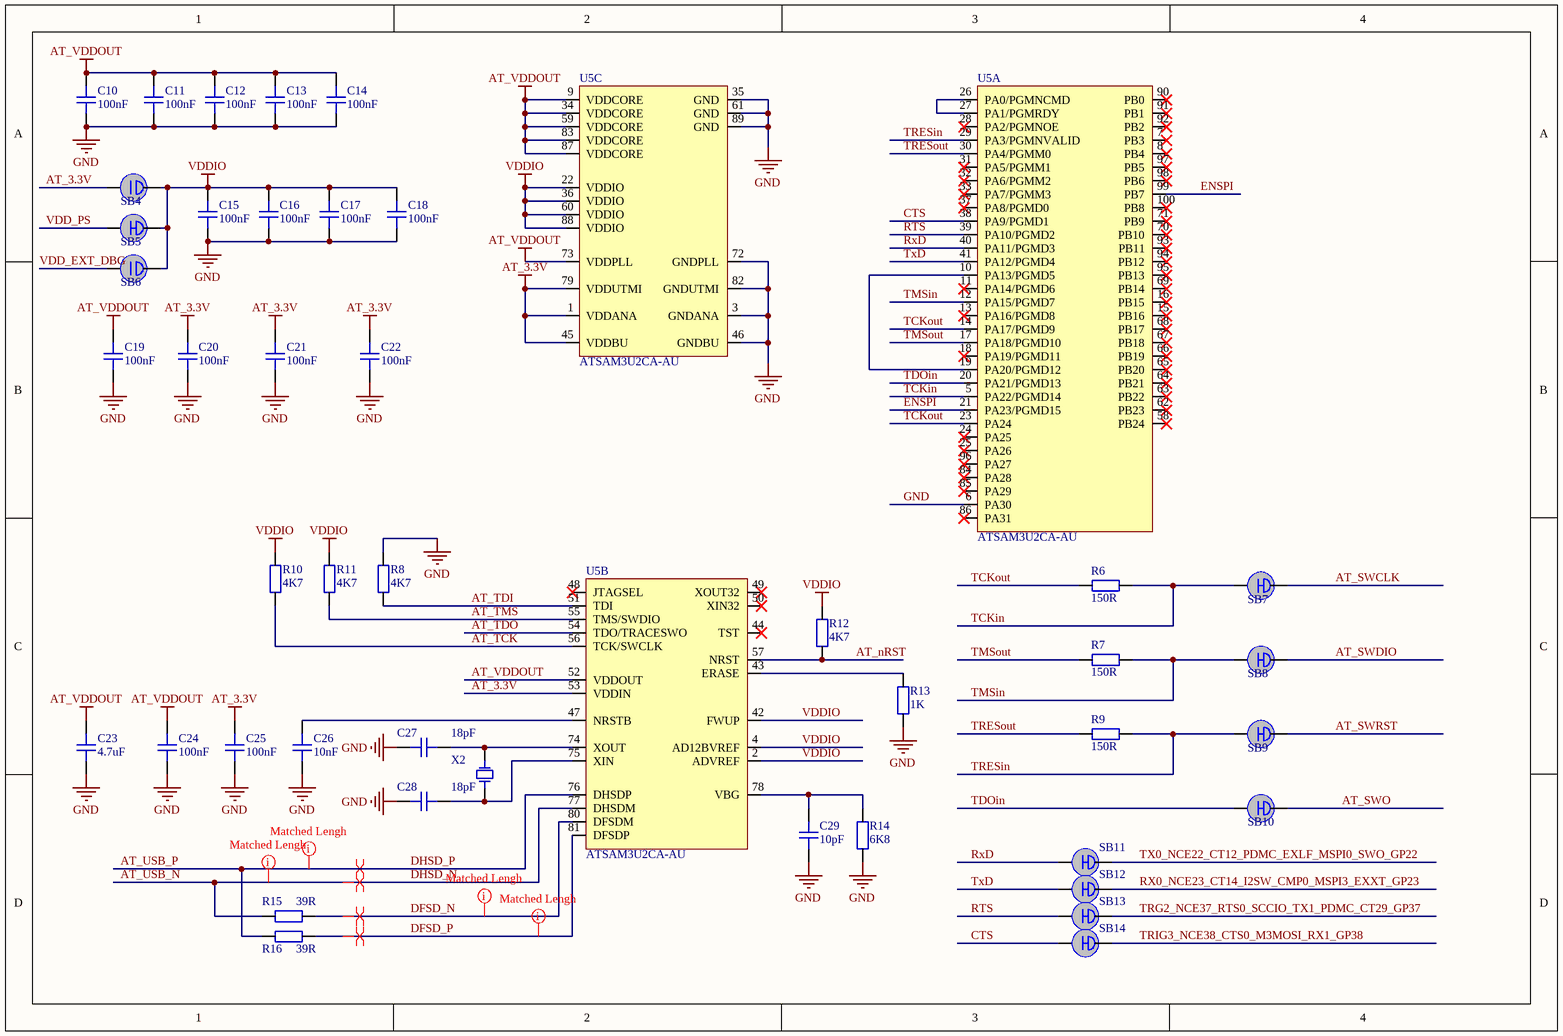
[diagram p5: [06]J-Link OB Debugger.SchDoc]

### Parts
C10  100nF  [CAPC1005L]
C11  100nF  [CAPC1005L]
C12  100nF  [CAPC1005L]
C13  100nF  [CAPC1005L]
C14  100nF  [CAPC1005L]
C15  100nF  [CAPC1005L]
C16  100nF  [CAPC1005L]
C17  100nF  [CAPC1005L]
C18  100nF  [CAPC1005L]
C19  100nF  [CAPC1005L]
C20  100nF  [CAPC1005L]
C21  100nF  [CAPC1005L]
C22  100nF  [CAPC1005L]
C23  4.7uF  [CAPC1005L]
C24  100nF  [CAPC1005L]
C25  100nF  [CAPC1005L]
C26  10nF  [CAPC1005L]
C27  18pF  [CAPC1005L]
C28  18pF  [CAPC1005L]
C29  10pF  [CAPC1005L]
R6  150R  [RESC1005L]
R7  150R  [RESC1005L]
R8  4K7  [RESC1005L]
R9  150R  [RESC1005L]
R10  4K7  [RESC1005L]
R11  4K7  [RESC1005L]
R12  4K7  [RESC1005L]
R13  1K  [RESC1005L]
R14  6K8  [RESC1005L]
R15  39R  [RESC1005L]
R16  39R  [RESC1005L]
SB4  SBO  [SBO]  (value not drawn)  (no BOM)
SB5  SBS  [SBS]  (value not drawn)  (net tie, no BOM)
SB6  SBO  [SBO]  (value not drawn)  (no BOM)
SB7  SBS  [SBS]  (value not drawn)  (net tie, no BOM)
SB8  SBS  [SBS]  (value not drawn)  (net tie, no BOM)
SB9  SBS  [SBS]  (value not drawn)  (net tie, no BOM)
SB10  SBS  [SBS]  (value not drawn)  (net tie, no BOM)
SB11  SBS  [SBS]  (value not drawn)  (net tie, no BOM)
SB12  SBS  [SBS]  (value not drawn)  (net tie, no BOM)
SB13  SBS  [SBS]  (value not drawn)  (net tie, no BOM)
SB14  SBS  [SBS]  (value not drawn)  (net tie, no BOM)
U5  ATSAM3U2CA-AU  [SQFP50P1600X1600-100L]  (parts A,B,C of 3)
X2  7M-12.000MAAJ-T  [OSCCC250X320X100L]  (value not drawn)

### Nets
AT_3.3V: C20.2 C21.2 C22.2 C25.2 SB4.1 U5.1(VDDANA) U5.45(VDDBU) U5.53(VDDIN) U5.79(VDDUTMI)
AT_VDDOUT: C10.2 C11.2 C12.2 C13.2 C14.2 C19.2 C23.2 C24.2 U5.9(VDDCORE) U5.34(VDDCORE) U5.52(VDDOUT) U5.59(VDDCORE) U5.73(VDDPLL) U5.83(VDDCORE) U5.87(VDDCORE)
GND: C10.1 C11.1 C12.1 C13.1 C14.1 C15.1 C16.1 C17.1 C18.1 C19.1 C20.1 C21.1 C22.1 C23.1 C24.1 C25.1 C26.1 C27.2 C28.2 C29.1 R8.2 R13.1 R14.2 U5.3(GNDANA) U5.6(PA30) U5.35(GND) U5.46(GNDBU) U5.61(GND) U5.72(GNDPLL) U5.82(GNDUTMI) U5.89(GND) X2.2 X2.4
VDDIO: C15.2 C16.2 C17.2 C18.2 R10.2 R11.2 R12.1 SB4.2 SB5.2 SB6.2 U5.2(ADVREF) U5.4(AD12BVREF) U5.22(VDDIO) U5.36(VDDIO) U5.42(FWUP) U5.60(VDDIO) U5.88(VDDIO)
AT_nRST: R12.2 U5.57(NRST)
AT_SWCLK: SB7.2
AT_SWDIO: SB8.2
AT_SWO: SB10.2
AT_SWRST: SB9.2
AT_TCK: R10.1 U5.56(TCK/SWCLK)
AT_TDI: R8.1 U5.51(TDI)
AT_TDO: U5.54(TDO/TRACESWO)
AT_TMS: R11.1 U5.55(TMS/SWDIO)
AT_USB_N: R15.2 U5.77(DHSDM)  [also labelled DHSD_N]
AT_USB_P: R16.2 U5.76(DHSDP)  [also labelled DHSD_P]
CTS: SB14.1 U5.38(PA9/PGMD1)
DFSD_N: R15.1 U5.80(DFSDM)
DFSD_P: R16.1 U5.81(DFSDP)
ENSPI: U5.21(PA23/PGMD15) U5.99(PB7)
RTS: SB13.1 U5.39(PA10/PGMD2)
RX0_NCE23_CT14_I2SW_CMP0_MSPI3_EXXT_GP23: SB12.2
RxD: SB11.1 U5.40(PA11/PGMD3)
TCKin: R6.1 SB7.1 U5.5(PA22/PGMD14)
TCKout: R6.2 U5.14(PA17/PGMD9) U5.23(PA24)
TDOin: SB10.1 U5.20(PA21/PGMD13)
TMSin: R7.1 SB8.1 U5.12(PA15/PGMD7)
TMSout: R7.2 U5.17(PA18/PGMD10)
TRESin: R9.1 SB9.1 U5.29(PA3/PGMNVALID)
TRESout: R9.2 U5.30(PA4/PGMM0)
TRG2_NCE37_RTS0_SCCIO_TX1_PDMC_CT29_GP37: SB13.2
TRIG3_NCE38_CTS0_M3MOSI_RX1_GP38: SB14.2
TX0_NCE22_CT12_PDMC_EXLF_MSPI0_SWO_GP22: SB11.2
TxD: SB12.1 U5.41(PA12/PGMD4)
VDD_EXT_DBG: SB6.1
VDD_PS: SB5.1
NetC26_2: C26.2 U5.47(NRSTB)
NetC27_1: C27.1 U5.74(XOUT) X2.3
NetC28_1: C28.1 U5.75(XIN) X2.1
NetC29_2: C29.2 R14.1 U5.78(VBG)
NetR13_2: R13.2 U5.43(ERASE)
NetU5_10: U5.10(PA13/PGMD5) U5.19(PA20/PGMD12)
NetU5_26: U5.26(PA0/PGMNCMD) U5.27(PA1/PGMRDY)

Not connected (* = marked no-connect by the designer): U5 7(PB3)* 8(PB4)* 11(PA14/PGMD6)* 13(PA16/PGMD8)* 15(PB16)* 16(PB15)* 18(PA19/PGMD11)* 24(PA25)* 25(PA26)* 28(PA2/PGMNOE)* 31(PA5/PGMM1)* 32(PA6/PGMM2)* 33(PA7/PGMM3)* 37(PA8/PGMD0)* 44(TST)* 48(JTAGSEL)* 49(XOUT32)* 50(XIN32)* 58(PB24)* 62(PB23)* 63(PB22)* 64(PB21)* 65(PB20)* 66(PB19)* 67(PB18)* 68(PB17)* 69(PB14)* 70(PB10)* 71(PB9)* 84(PA28)* 85(PA29)* 86(PA31)* 90(PB0)* 91(PB1)* 92(PB2)* 93(PB11)* 94(PB12)* 95(PB13)* 96(PA27)* 97(PB5)* 98(PB6)* 100(PB8)*

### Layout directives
differential pair: AT_USB_N, AT_USB_P, DFSD_N, DFSD_P
rule Matched Net Lengths [Tolerance = 50mil]: AT_USB_N, AT_USB_P, DFSD_N, DFSD_P

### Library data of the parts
C10-C29 = CAP_CHP: Surface Mount Unpolarized Capacitor
R6-R16 = RES_CHP: Surface Mount Resistor
SB4 SB6 = SBO: Open-circuit soldering bridge
SB5 SB7-SB14 = SBS: Short-circuit soldering bridge
U5 = ATSAM3U2CA: Atmel ¦ SMART ARM-based Flash MCU
X2 = XTAL_SMD_4PIN: XTAL 12MHz ±30ppm 18pF 100 Ohm -20°C ~ 70°C SMD 3225

## Sheet [07]User Interface.SchDoc
size A4; Organization: Altium Limited; Address1: L3, 12a Rodborough Rd; Address2: Frenchs Forest; Address3: NSW; Address4: Australia 2086
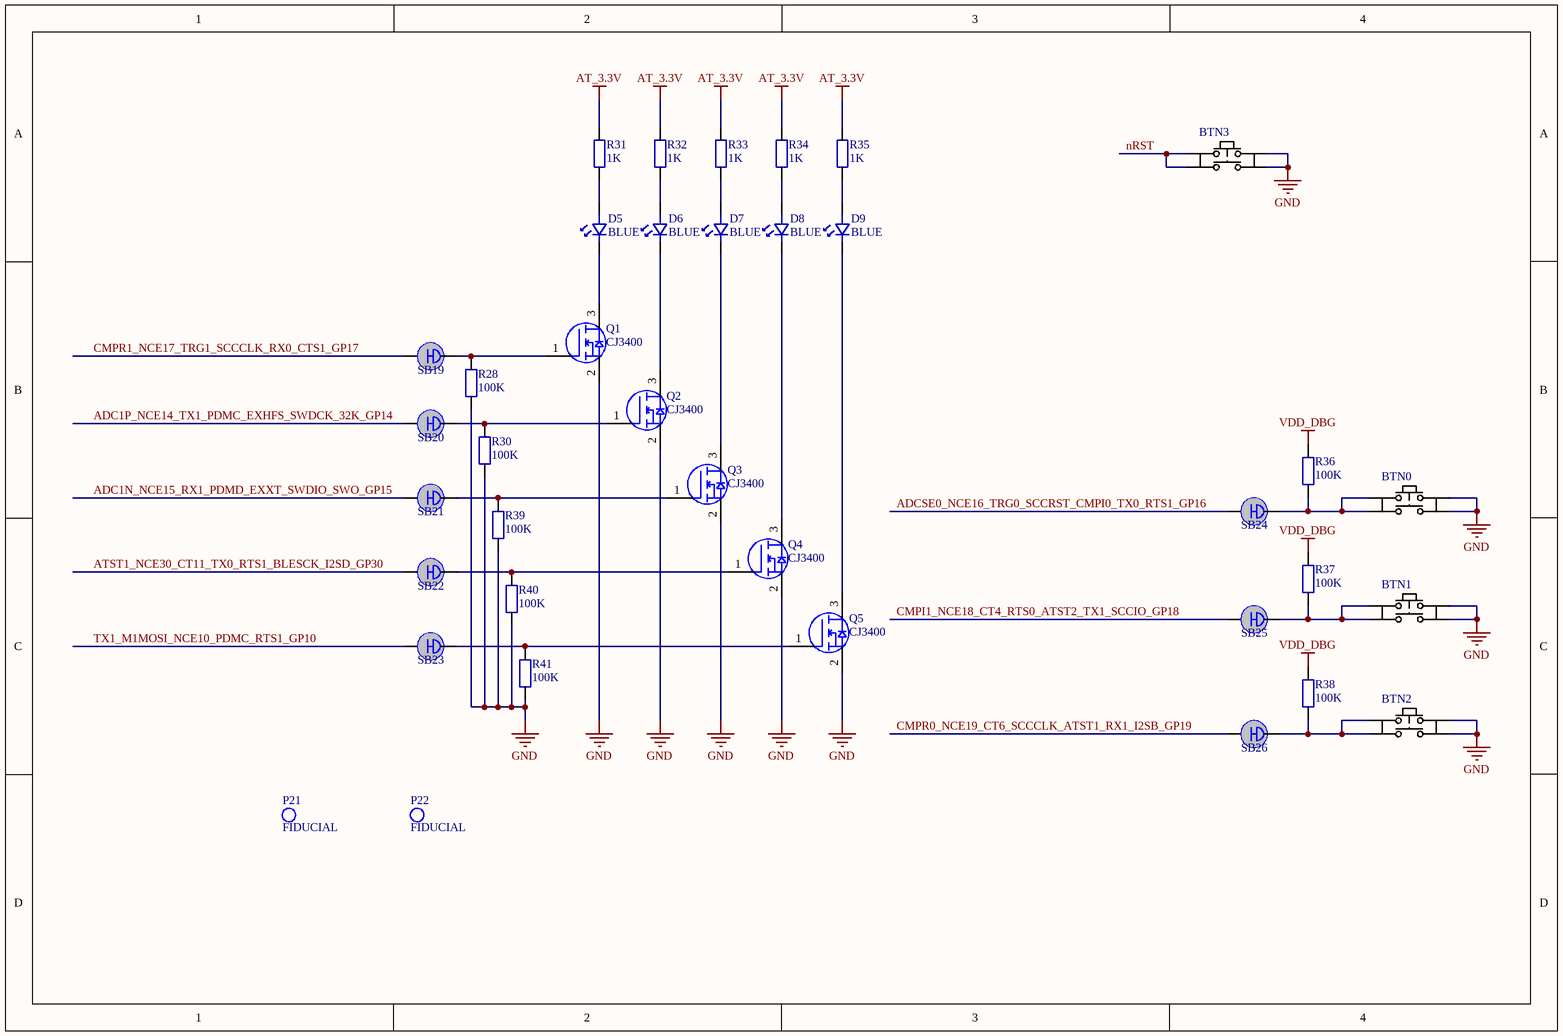
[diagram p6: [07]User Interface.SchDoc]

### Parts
BTN0  KFC-D003(4.3mm)  [TACT_TOP]  (value not drawn)
BTN1  KFC-D003(4.3mm)  [TACT_TOP]  (value not drawn)
BTN2  KFC-D003(4.3mm)  [TACT_TOP]  (value not drawn)
BTN3  KFC-D003(4.3mm)  [TACT_TOP]  (value not drawn)
D5  BLUE  [LEDC1608L]
D6  BLUE  [LEDC1608L]
D7  BLUE  [LEDC1608L]
D8  BLUE  [LEDC1608L]
D9  BLUE  [LEDC1608L]
P21  FIDUCIAL  [Fiducial]  (no BOM)
P22  FIDUCIAL  [Fiducial]  (no BOM)
Q1  CJ3400  [SOT23-3L]
Q2  CJ3400  [SOT23-3L]
Q3  CJ3400  [SOT23-3L]
Q4  CJ3400  [SOT23-3L]
Q5  CJ3400  [SOT23-3L]
R28  100K  [RESC1005L]
R30  100K  [RESC1005L]
R31  1K  [RESC1005L]
R32  1K  [RESC1005L]
R33  1K  [RESC1005L]
R34  1K  [RESC1005L]
R35  1K  [RESC1005L]
R36  100K  [RESC1005L]
R37  100K  [RESC1005L]
R38  100K  [RESC1005L]
R39  100K  [RESC1005L]
R40  100K  [RESC1005L]
R41  100K  [RESC1005L]
SB19  SBS  [SBS]  (value not drawn)  (net tie, no BOM)
SB20  SBS  [SBS]  (value not drawn)  (net tie, no BOM)
SB21  SBS  [SBS]  (value not drawn)  (net tie, no BOM)
SB22  SBS  [SBS]  (value not drawn)  (net tie, no BOM)
SB23  SBS  [SBS]  (value not drawn)  (net tie, no BOM)
SB24  SBS  [SBS]  (value not drawn)  (net tie, no BOM)
SB25  SBS  [SBS]  (value not drawn)  (net tie, no BOM)
SB26  SBS  [SBS]  (value not drawn)  (net tie, no BOM)

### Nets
AT_3.3V: R31.2 R32.2 R33.2 R34.2 R35.2
GND: BTN0.1 BTN0.4 BTN1.1 BTN1.4 BTN2.1 BTN2.4 BTN3.1 BTN3.4 Q1.2 Q2.2 Q3.2 Q4.2 Q5.2 R28.1 R30.1 R39.1 R40.1 R41.1
VDD_DBG: R36.2 R37.2 R38.2
ADC1N_NCE15_RX1_PDMD_EXXT_SWDIO_SWO_GP15: SB21.1
ADC1P_NCE14_TX1_PDMC_EXHFS_SWDCK_32K_GP14: SB20.1
ADCSE0_NCE16_TRG0_SCCRST_CMPI0_TX0_RTS1_GP16: SB24.1
ATST1_NCE30_CT11_TX0_RTS1_BLESCK_I2SD_GP30: SB22.1
CMPI1_NCE18_CT4_RTS0_ATST2_TX1_SCCIO_GP18: SB25.1
CMPR0_NCE19_CT6_SCCCLK_ATST1_RX1_I2SB_GP19: SB26.1
CMPR1_NCE17_TRG1_SCCCLK_RX0_CTS1_GP17: SB19.1
nRST: BTN3.2 BTN3.3  [project net AT_SWRST]
TX1_M1MOSI_NCE10_PDMC_RTS1_GP10: SB23.1
NetBTN0_2: BTN0.2 BTN0.3 R36.1 SB24.2
NetBTN1_2: BTN1.2 BTN1.3 R37.1 SB25.2
NetBTN2_2: BTN2.2 BTN2.3 R38.1 SB26.2
NetD5_1: D5.1 Q1.3
NetD5_2: D5.2 R31.1
NetD6_1: D6.1 Q2.3
NetD6_2: D6.2 R32.1
NetD7_1: D7.1 Q3.3
NetD7_2: D7.2 R33.1
NetD8_1: D8.1 Q4.3
NetD8_2: D8.2 R34.1
NetD9_1: D9.1 Q5.3
NetD9_2: D9.2 R35.1
NetQ1_1: Q1.1 R28.2 SB19.2
NetQ2_1: Q2.1 R30.2 SB20.2
NetQ3_1: Q3.1 R39.2 SB21.2
NetQ4_1: Q4.1 R40.2 SB22.2
NetQ5_1: Q5.1 R41.2 SB23.2

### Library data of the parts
BTN0-BTN3 = TACT_4PIN: Tactile Switch SPST-NO Top Actuated Surface Mount
D5-D9 = LED_SMD: Surface Mount LED
P21 P22 = FIDUCIAL: SMT Fiducial
Q1-Q5 = MOS_N: N-Channel MOSFET
R28 R30-R41 = RES_CHP: Surface Mount Resistor
SB19-SB26 = SBS: Short-circuit soldering bridge

## Sheet [08]Debug Headers and Support.SchDoc
size A4; Organization: Altium Limited; Address1: L3, 12a Rodborough Rd; Address2: Frenchs Forest; Address3: NSW; Address4: Australia 2086
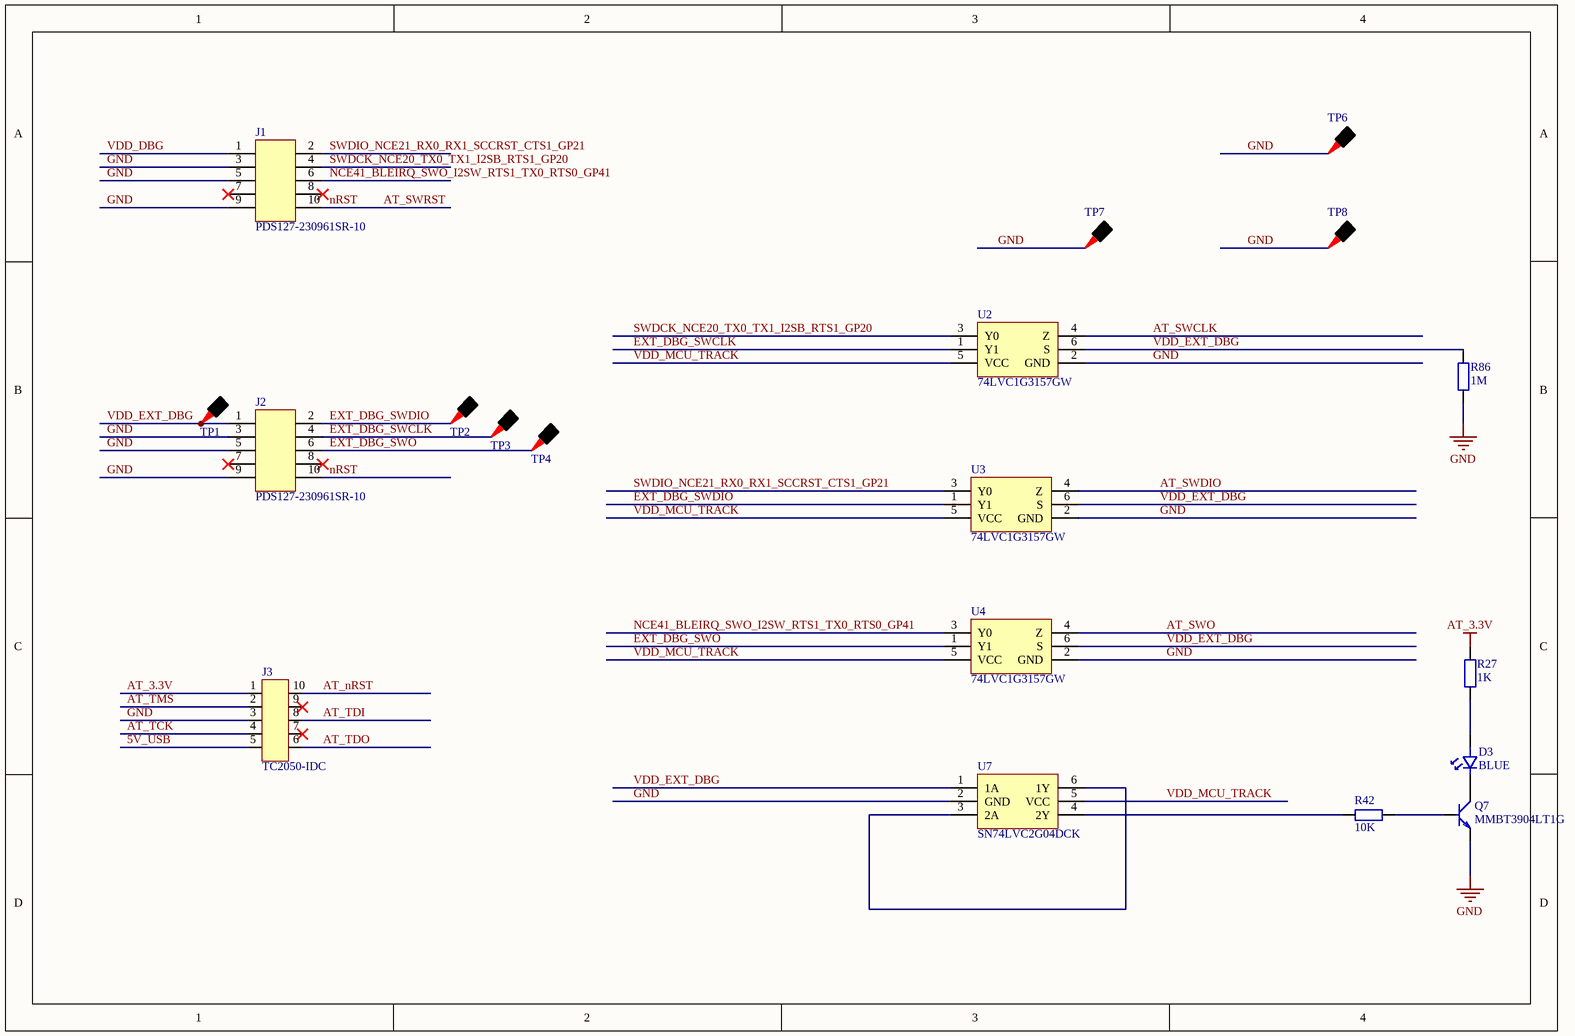
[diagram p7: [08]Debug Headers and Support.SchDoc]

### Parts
D3  BLUE  [LEDC1608L]
J1  PDS127-230961SR-10  [FTSH-105]
J2  PDS127-230961SR-10  [FTSH-105]
J3  TC2050-IDC  [TC2050-IDC]  (no BOM)
Q7  MMBT3904LT1G  [SOT23-3L]
R27  1K  [RESC1005L]
R42  10K  [RESC1005L]
R86  1M  [RESC1005L]
TP1  Test Point  [TP_TH_10_20]  (value not drawn)  (no BOM)
TP2  Test Point  [TP_TH_10_20]  (value not drawn)  (no BOM)
TP3  Test Point  [TP_TH_10_20]  (value not drawn)  (no BOM)
TP4  Test Point  [TP_TH_10_20]  (value not drawn)  (no BOM)
TP6  5016  [5016]  (value not drawn)
TP7  5016  [5016]  (value not drawn)
TP8  5016  [5016]  (value not drawn)
U2  74LVC1G3157GW  [SOT363-6L]
U3  74LVC1G3157GW  [SOT363-6L]
U4  74LVC1G3157GW  [SOT363-6L]
U7  SN74LVC2G04DCK  [SOT363-6L]

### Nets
5V_USB: J3.5
AT_3.3V: J3.1 R27.2
GND: J1.3 J1.5 J1.9 J2.3 J2.5 J2.9 J3.3 Q7.2 R86.1 TP6.1 TP7.1 TP8.1 U2.2(GND) U3.2(GND) U4.2(GND) U7.2(GND)
VDD_DBG: J1.1
VDD_MCU_TRACK: U2.5(VCC) U3.5(VCC) U4.5(VCC) U7.5(VCC)
AT_nRST: J3.10
AT_SWCLK: U2.4(Z)
AT_SWDIO: U3.4(Z)
AT_SWO: U4.4(Z)
AT_SWRST: J1.10 J2.10  [also labelled nRST]
AT_TCK: J3.4
AT_TDI: J3.8
AT_TDO: J3.6
AT_TMS: J3.2
EXT_DBG_SWCLK: J2.4 TP3.1 U2.1(Y1)
EXT_DBG_SWDIO: J2.2 TP2.1 U3.1(Y1)
EXT_DBG_SWO: J2.6 TP4.1 U4.1(Y1)
NCE41_BLEIRQ_SWO_I2SW_RTS1_TX0_RTS0_GP41: J1.6 U4.3(Y0)
SWDCK_NCE20_TX0_TX1_I2SB_RTS1_GP20: J1.4 U2.3(Y0)
SWDIO_NCE21_RX0_RX1_SCCRST_CTS1_GP21: J1.2 U3.3(Y0)
VDD_EXT_DBG: J2.1 R86.2 TP1.1 U2.6(S) U3.6(S) U4.6(S) U7.1(1A)
NetD3_1: D3.1 Q7.3
NetD3_2: D3.2 R27.1
NetQ7_1: Q7.1 R42.2
NetR42_1: R42.1 U7.4(2Y)
NetU7_3: U7.3(2A) U7.6(1Y)

Not connected (* = marked no-connect by the designer): J1 7* 8*; J2 7* 8*; J3 7* 9*

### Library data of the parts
D3 = LED_SMD: Surface Mount LED
J1 J2 = FTSH-105: 10 Positions Header, Unshrouded Connector 1.27mm SMD Gold
Q7 = TRAN_NPN: Surface Mount NPN Transistor
R27 R42 R86 = RES_CHP: Surface Mount Resistor
TP1-TP4 = TP
TP6-TP8 = TP: Test Point
U2-U4 = 74LVC1G3157GW: 2-channel analog multiplexer/demultiplexer
U7 = 74LVC2G04: Dual Inverter

## Sheet [09]USBHub.SchDoc
size A4
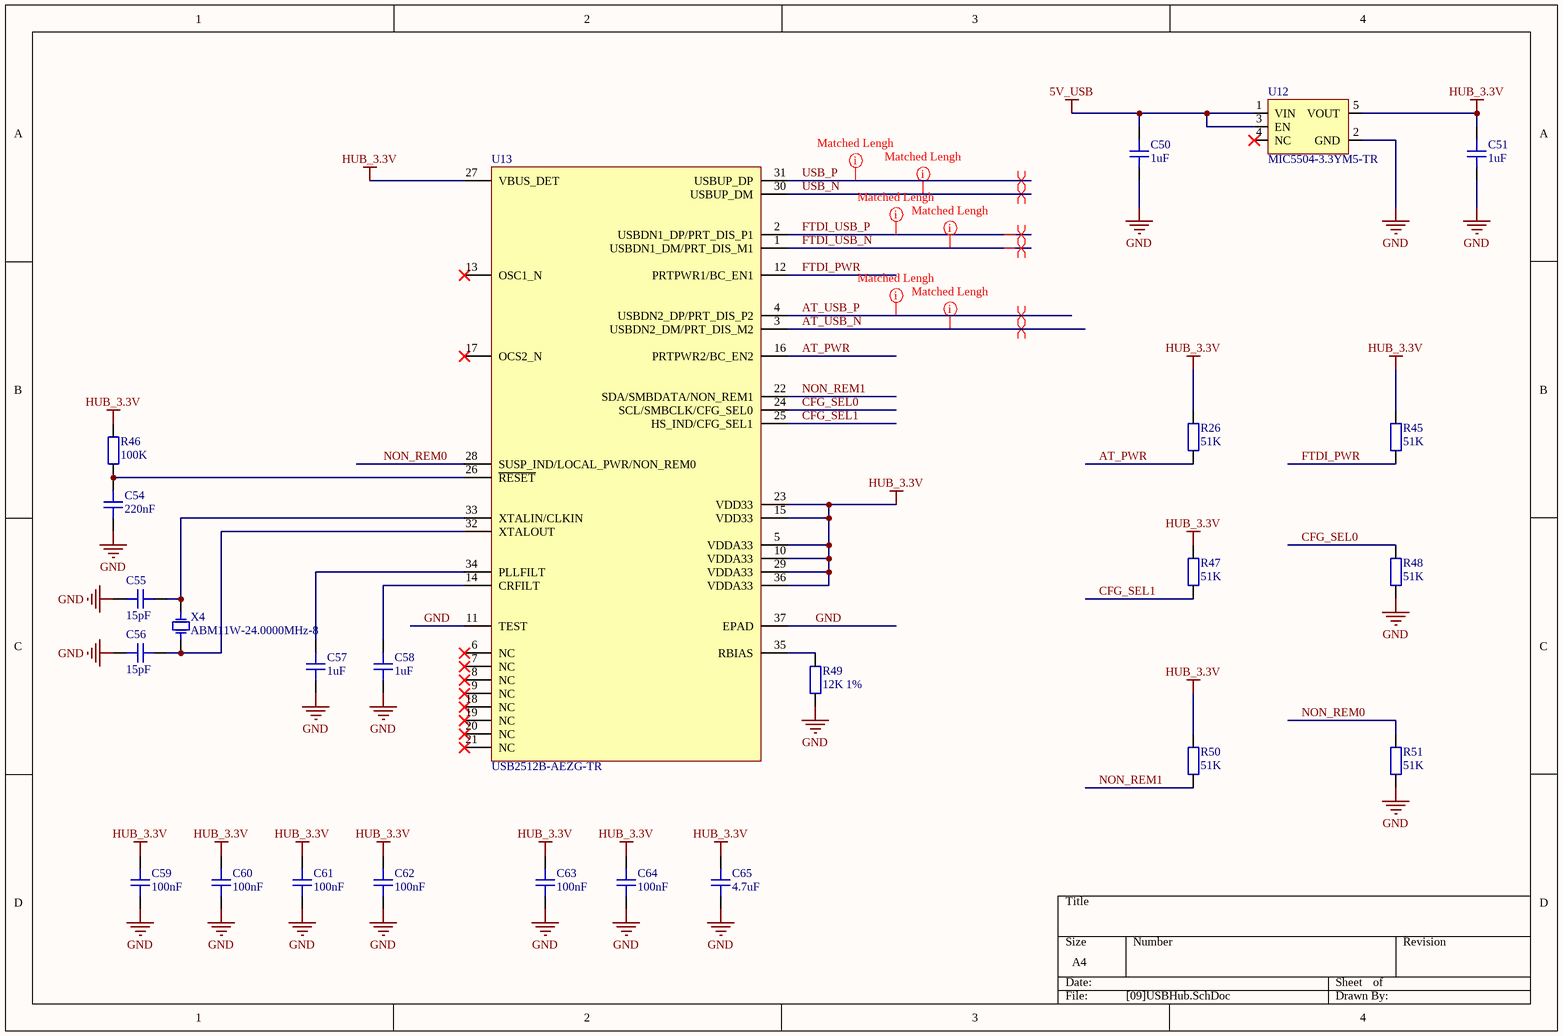
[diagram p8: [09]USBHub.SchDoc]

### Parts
C50  1uF  [CAPC1005L]
C51  1uF  [CAPC1005L]
C54  220nF  [CAPC1005L]
C55  15pF  [CAPC1005L]
C56  15pF  [CAPC1005L]
C57  1uF  [CAPC1005L]
C58  1uF  [CAPC1005L]
C59  100nF  [CAPC1005L]
C60  100nF  [CAPC1005L]
C61  100nF  [CAPC1005L]
C62  100nF  [CAPC1005L]
C63  100nF  [CAPC1005L]
C64  100nF  [CAPC1005L]
C65  4.7uF  [CAPC1005L]
R26  51K  [RESC1005L]
R45  51K  [RESC1005L]
R46  100K  [RESC1005L]
R47  51K  [RESC1005L]
R48  51K  [RESC1005L]
R49  12K 1%  [RESC1005L]
R50  51K  [RESC1005L]
R51  51K  [RESC1005L]
U12  MIC5504-3.3YM5-TR  [SOT23-5_L]
U13  USB2512B-AEZG-TR  [QFN50P600X600-36V4L]
X4  ABM11W-24.0000MHz-8  [OSCCC160X200X100]

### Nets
5V_USB: C50.2 U12.1(VIN) U12.3(EN)
GND: C50.1 C51.1 C54.1 C55.2 C56.2 C57.1 C58.1 C59.1 C60.1 C61.1 C62.1 C63.1 C64.1 C65.1 R48.1 R49.1 R51.1 U12.2(GND) U13.11(TEST) U13.37(EPAD) X4.2 X4.4
HUB_3.3V: C51.2 C59.2 C60.2 C61.2 C62.2 C63.2 C64.2 C65.2 R26.2 R45.2 R46.2 R47.2 R50.2 U12.5(VOUT) U13.5(VDDA33) U13.10(VDDA33) U13.15(VDD33) U13.23(VDD33) U13.27(VBUS_DET) U13.29(VDDA33) U13.36(VDDA33)
AT_PWR: R26.1 U13.16(PRTPWR2/BC_EN2)
AT_USB_N: U13.3(USBDN2_DM/PRT_DIS_M2)
AT_USB_P: U13.4(USBDN2_DP/PRT_DIS_P2)
CFG_SEL0: R48.2 U13.24(SCL/SMBCLK/CFG_SEL0)
CFG_SEL1: R47.1 U13.25(HS_IND/CFG_SEL1)
FTDI_PWR: R45.1 U13.12(PRTPWR1/BC_EN1)
FTDI_USB_N: U13.1(USBDN1_DM/PRT_DIS_M1)
FTDI_USB_P: U13.2(USBDN1_DP/PRT_DIS_P1)
NON_REM0: R51.2 U13.28(SUSP_IND/LOCAL_PWR/NON_REM0)
NON_REM1: R50.1 U13.22(SDA/SMBDATA/NON_REM1)
USB_N: U13.30(USBUP_DM)
USB_P: U13.31(USBUP_DP)
NetC54_2: C54.2 R46.1 U13.26(~{RESET})
NetC55_1: C55.1 U13.33(XTALIN/CLKIN) X4.3
NetC56_1: C56.1 U13.32(XTALOUT) X4.1
NetC57_2: C57.2 U13.34(PLLFILT)
NetC58_2: C58.2 U13.14(CRFILT)
NetR49_2: R49.2 U13.35(RBIAS)

Not connected (* = marked no-connect by the designer): U12 4(NC)*; U13 6(NC)* 7(NC)* 8(NC)* 9(NC)* 13(OSC1_N)* 17(OCS2_N)* 18(NC)* 19(NC)* 20(NC)* 21(NC)*

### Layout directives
differential pair: AT_USB_N, AT_USB_P, FTDI_USB_N, FTDI_USB_P, USB_N, USB_P
rule Matched Net Lengths [Tolerance = 50mil]: AT_USB_N, AT_USB_P, FTDI_USB_N, FTDI_USB_P, USB_N, USB_P

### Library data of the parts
C50 C51 C54-C65 = CAP_CHP: Surface Mount Unpolarized Capacitor
R26 R45-R51 = RES_CHP: Surface Mount Resistor
U12 = MIC5504-3.3YM5-TR: as U11 on sheet [04]Power Supplies
U13 = USB2512B: USB 2.0 High-Speed 2-Port Hub Controller
X4 = XTAL_SMD_4PIN: Surface Mount Crystal

## Sheet [10]USBSPIBridge.SchDoc
size A4
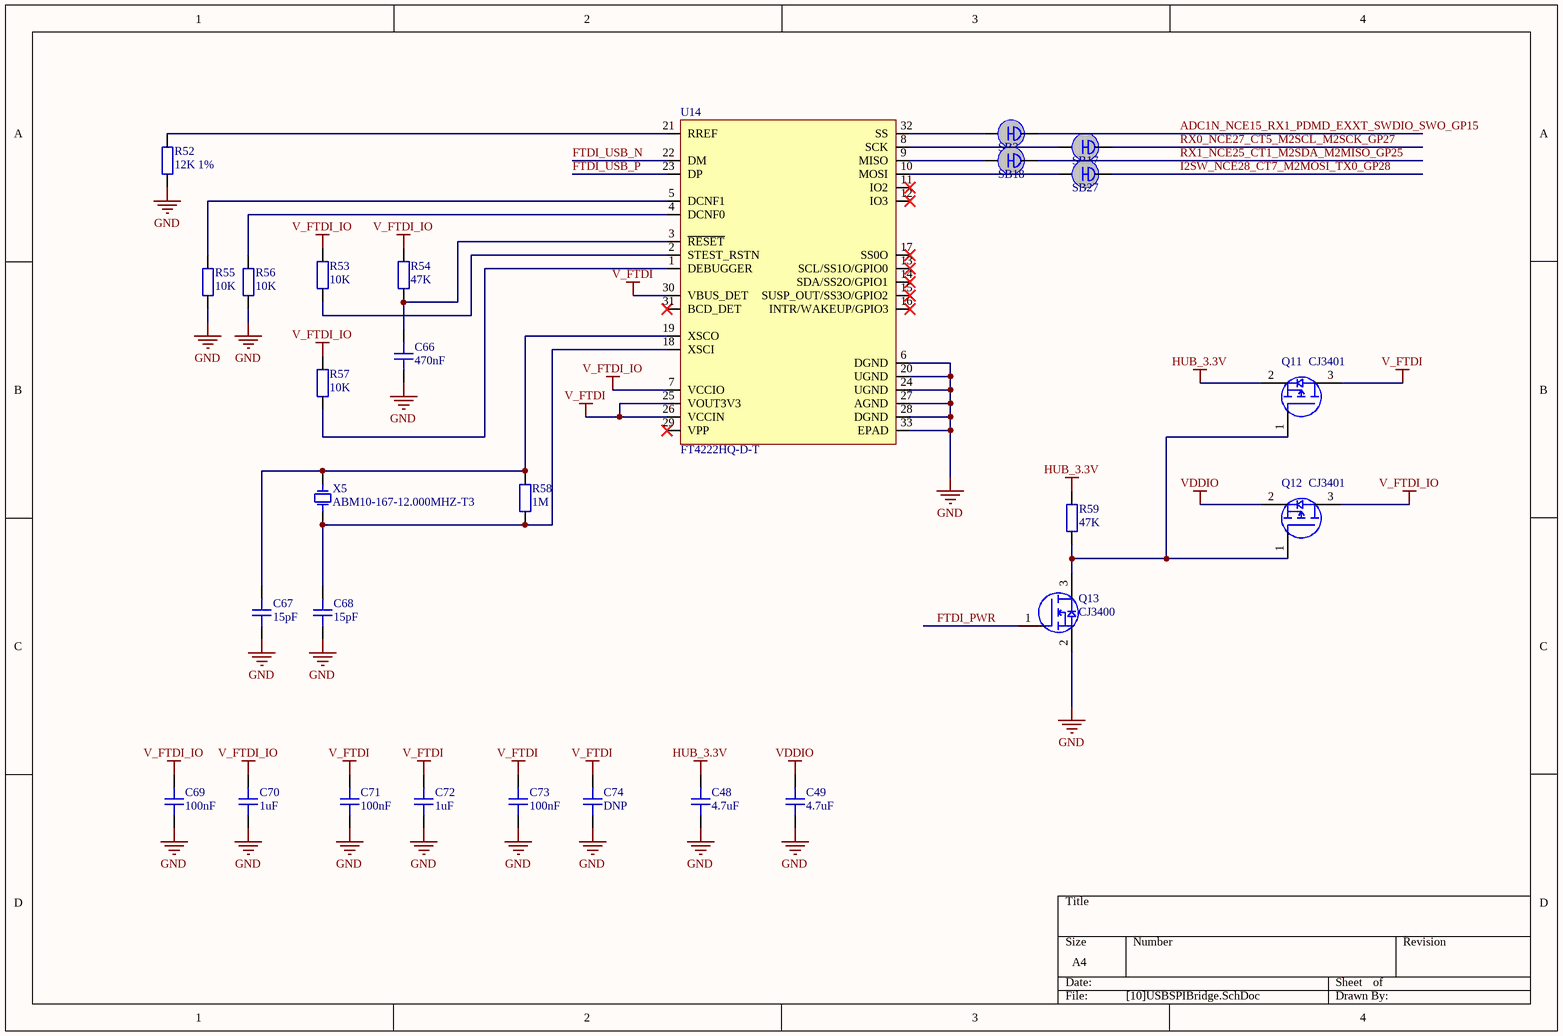
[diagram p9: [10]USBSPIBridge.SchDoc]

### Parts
C48  4.7uF  [CAPC1005L]
C49  4.7uF  [CAPC1005L]
C66  470nF  [CAPC1005L]
C67  15pF  [CAPC1005L]
C68  15pF  [CAPC1005L]
C69  100nF  [CAPC1005L]
C70  1uF  [CAPC1005L]
C71  100nF  [CAPC1005L]
C72  1uF  [CAPC1005L]
C73  100nF  [CAPC1005L]
C74  DNP  [CAPC1005L]
Q11  CJ3401  [SOT23-3L]
Q12  CJ3401  [SOT23-3L]
Q13  CJ3400  [SOT23-3L]
R52  12K 1%  [RESC1005L]
R53  10K  [RESC1005L]
R54  47K  [RESC1005L]
R55  10K  [RESC1005L]
R56  10K  [RESC1005L]
R57  10K  [RESC1005L]
R58  1M  [RESC1005L]
R59  47K  [RESC1005L]
SB3  SBS  [SBS]  (value not drawn)  (net tie, no BOM)
SB17  SBS  [SBS]  (value not drawn)  (net tie, no BOM)
SB18  SBS  [SBS]  (value not drawn)  (net tie, no BOM)
SB27  SBS  [SBS]  (value not drawn)  (net tie, no BOM)
U14  FT4222HQ-D-T  [QFN50P500X500-32W2N]
X5  ABM10-167-12.000MHZ-T3  [OSCCC200X250X100]

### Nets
GND: C48.1 C49.1 C66.1 C67.2 C68.2 C69.1 C70.1 C71.1 C72.1 C73.1 C74.1 Q13.2 R52.1 R55.1 R56.1 U14.6(DGND) U14.20(UGND) U14.24(UGND) U14.27(AGND) U14.28(DGND) U14.33(EPAD) X5.2 X5.4
HUB_3.3V: C48.2 Q11.2 R59.2
V_FTDI: C71.2 C72.2 C73.2 C74.2 Q11.3 U14.25(VOUT3V3) U14.26(VCCIN) U14.30(VBUS_DET)
V_FTDI_IO: C69.2 C70.2 Q12.3 R53.2 R54.2 R57.2 U14.7(VCCIO)
VDDIO: C49.2 Q12.2
ADC1N_NCE15_RX1_PDMD_EXXT_SWDIO_SWO_GP15: SB3.2
FTDI_PWR: Q13.1
FTDI_USB_N: U14.22(DM)
FTDI_USB_P: U14.23(DP)
I2SW_NCE28_CT7_M2MOSI_TX0_GP28: SB27.2
RX0_NCE27_CT5_M2SCL_M2SCK_GP27: SB17.2
RX1_NCE25_CT1_M2SDA_M2MISO_GP25: SB18.2
NetC66_2: C66.2 R54.1 U14.3(~{RESET})
NetC67_1: C67.1 R58.2 U14.19(XSCO) X5.1
NetC68_1: C68.1 R58.1 U14.18(XSCI) X5.3
NetQ11_1: Q11.1 Q12.1 Q13.3 R59.1
NetR52_2: R52.2 U14.21(RREF)
NetR53_1: R53.1 U14.2(STEST_RSTN)
NetR55_2: R55.2 U14.5(DCNF1)
NetR56_2: R56.2 U14.4(DCNF0)
NetR57_1: R57.1 U14.1(DEBUGGER)
NetSB3_1: SB3.1 U14.32(SS)
NetSB17_1: SB17.1 U14.8(SCK)
NetSB18_1: SB18.1 U14.9(MISO)
NetSB27_1: SB27.1 U14.10(MOSI)

Not connected (* = marked no-connect by the designer): U14 11(IO2)* 12(IO3)* 13(SCL/SS1O/GPIO0)* 14(SDA/SS2O/GPIO1)* 15(SUSP_OUT/SS3O/GPIO2)* 16(INTR/WAKEUP/GPIO3)* 17(SS0O)* 29(VPP)* 31(BCD_DET)*

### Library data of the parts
C48 C49 C66-C74 = CAP_CHP: Surface Mount Unpolarized Capacitor
Q11 Q12 = MOS_P: P-Channel MOSFET
Q13 = MOS_N: N-Channel MOSFET
R52-R59 = RES_CHP: Surface Mount Resistor
SB3 SB17 SB18 SB27 = SBS: Short-circuit soldering bridge
U14 = FT4222: FT4222H USB2.0 TO QUADSPI/I2C BRIDGE IC
X5 = XTAL_SMD_4PIN: Surface Mount Crystal

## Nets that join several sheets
5V_USB: [02]Arduino Headers (P12.5), [03]Breakout Headers (P3.5 P4.5), [04]Power Supplies (10 pins), [05]Power Supply Tracker (5 pins), [08]Debug Headers and Support (J3.5), [09]USBHub (C50.2 U12.1 U12.3)
AT_3.3V: [04]Power Supplies (C35.2 P20.5 P20.6 U11.5), [06]J-Link OB Debugger (9 pins), [07]User Interface (5 pins), [08]Debug Headers and Support (J3.1 R27.2)
GND: [01]MCU (32 pins), [02]Arduino Headers (8 pins), [03]Breakout Headers (5 pins), [04]Power Supplies (30 pins), [05]Power Supply Tracker (9 pins), [06]J-Link OB Debugger (33 pins), [07]User Interface (18 pins), [08]Debug Headers and Support (16 pins), [09]USBHub (22 pins), [10]USBSPIBridge (23 pins)
HUB_3.3V: [09]USBHub (21 pins), [10]USBSPIBridge (C48.2 Q11.2 R59.2)
VDD_DBG: [02]Arduino Headers (P16.1 P16.3), [05]Power Supply Tracker (SB84.2 SB85.2), [07]User Interface (R36.2 R37.2 R38.2), [08]Debug Headers and Support (J1.1)
VDD_MCU: [01]MCU (10 pins), [04]Power Supplies (P19.2 SB15.2), [05]Power Supply Tracker (R79.1 SB85.1)
VDD_MCU_TRACK: [01]MCU (R1.1 R3.1), [05]Power Supply Tracker (8 pins), [08]Debug Headers and Support (U2.5 U3.5 U4.5 U7.5)
VDDIO: [06]J-Link OB Debugger (17 pins), [10]USBSPIBridge (C49.2 Q12.2)
32K_NCE47_CT26_M5MOSI_RX1_GP47: [01]MCU (U1.H10), [02]Arduino Headers (P13.11), [03]Breakout Headers (P5.6)
ADC0NSE9_NCE12_CT0_SCE_PDMC_CTS0_TX1_GP12: [01]MCU (U1.A7), [02]Arduino Headers (P17.15), [03]Breakout Headers (P9.8)
ADC0PSE8_NCE13_CT2_I2SB_EXHFB_RTS0_RX1_GP13: [01]MCU (U1.B7), [02]Arduino Headers (P14.1), [03]Breakout Headers (P7.1 P8.1)
ADC1N_NCE15_RX1_PDMD_EXXT_SWDIO_SWO_GP15: [01]MCU (U1.C6), [02]Arduino Headers (P18.7), [07]User Interface (SB21.1), [10]USBSPIBridge (SB3.2)
ADC1P_NCE14_TX1_PDMC_EXHFS_SWDCK_32K_GP14: [01]MCU (U1.C7), [02]Arduino Headers (P18.9), [07]User Interface (SB20.1)
ADCSE0_NCE16_TRG0_SCCRST_CMPI0_TX0_RTS1_GP16: [01]MCU (U1.F3), [02]Arduino Headers (P18.6), [07]User Interface (SB24.1)
ADCSE1_NCE29_CT9_CTS0_CTS1_RX0_PDMD_GP29: [01]MCU (U1.A5), [02]Arduino Headers (P14.2), [03]Breakout Headers (P7.2 P8.2)
ADCSE2_NCE11_CT31_SINT_CTS1_RX0_PDMD_GP11: [01]MCU (U1.B5), [02]Arduino Headers (P14.3), [03]Breakout Headers (P7.3 P8.3)
ADCSE3_NCE31_CT13_RX0_SCCCLK_BLEMISO_RTS1_GP31: [01]MCU (U1.D5), [02]Arduino Headers (P14.4), [03]Breakout Headers (P7.4 P8.4)
ADCSE4_NCE32_CT15_SCCIO_EXLF_BLEMOSI_CTS1_GP32: [01]MCU (U1.B6), [02]Arduino Headers (P14.5), [03]Breakout Headers (P7.5 P8.5)
ADCSE5_NCE33_32K_BLECSN_CTS0_CT23_SWO_GP33: [01]MCU (U1.C5), [02]Arduino Headers (P14.6), [03]Breakout Headers (P7.6 P8.6)
ADCSE6_NCE34_RTS1_CMPR2_RTS0_RX0_PDMD_GP34: [01]MCU (U1.D6), [02]Arduino Headers (P14.7), [03]Breakout Headers (P7.7 P8.7)
ADCSE7_NCE35_TX1_I2SD_CT27_RTS0_BLESTATUS_GP35: [01]MCU (U1.E4), [02]Arduino Headers (P14.8), [03]Breakout Headers (P7.8 P8.8)
AT_nRST: [06]J-Link OB Debugger (R12.2 U5.57), [08]Debug Headers and Support (J3.10)
AT_PWR: [04]Power Supplies (U11.3), [09]USBHub (R26.1 U13.16)
AT_SWCLK: [06]J-Link OB Debugger (SB7.2), [08]Debug Headers and Support (U2.4)
AT_SWDIO: [06]J-Link OB Debugger (SB8.2), [08]Debug Headers and Support (U3.4)
AT_SWO: [06]J-Link OB Debugger (SB10.2), [08]Debug Headers and Support (U4.4)
AT_SWRST: [01]MCU (R3.2 U1.G7), [02]Arduino Headers (P12.3 P15.5 P18.13), [03]Breakout Headers (P3.3 P4.3), [06]J-Link OB Debugger (SB9.2), [07]User Interface (BTN3.2 BTN3.3), [08]Debug Headers and Support (J1.10 J2.10)
AT_TCK: [06]J-Link OB Debugger (R10.1 U5.56), [08]Debug Headers and Support (J3.4)
AT_TDI: [06]J-Link OB Debugger (R8.1 U5.51), [08]Debug Headers and Support (J3.8)
AT_TDO: [06]J-Link OB Debugger (U5.54), [08]Debug Headers and Support (J3.6)
AT_TMS: [06]J-Link OB Debugger (R11.1 U5.55), [08]Debug Headers and Support (J3.2)
AT_USB_N: [06]J-Link OB Debugger (R15.2 U5.77), [09]USBHub (U13.3)
AT_USB_P: [06]J-Link OB Debugger (R16.2 U5.76), [09]USBHub (U13.4)
ATST1_NCE30_CT11_TX0_RTS1_BLESCK_I2SD_GP30: [01]MCU (U1.F4), [02]Arduino Headers (P18.5), [07]User Interface (SB22.1)
CMPI1_NCE18_CT4_RTS0_ATST2_TX1_SCCIO_GP18: [01]MCU (U1.D4), [02]Arduino Headers (P18.8), [07]User Interface (SB25.1)
CMPR0_NCE19_CT6_SCCCLK_ATST1_RX1_I2SB_GP19: [01]MCU (U1.F2), [02]Arduino Headers (P18.10), [07]User Interface (SB26.1)
CMPR1_NCE17_TRG1_SCCCLK_RX0_CTS1_GP17: [01]MCU (U1.E3), [02]Arduino Headers (P18.11), [07]User Interface (SB19.1)
CST1_NCE45_CT22_I2SD_PDMD_RX0_SWO_GP45: [01]MCU (U1.H8), [02]Arduino Headers (P13.15), [03]Breakout Headers (P5.8)
CTS0_SINT_NCE4_RX1_CT17_MISP2_GP4: [01]MCU (U1.A11), [02]Arduino Headers (P15.7)
EXHF_NCE26_CT3_SCCRST_MSPI1_TX0_CTS1_GP26: [01]MCU (U1.A10), [02]Arduino Headers (P13.5), [03]Breakout Headers (P5.3)
FTDI_PWR: [09]USBHub (R45.1 U13.12), [10]USBSPIBridge (Q13.1)
FTDI_USB_N: [09]USBHub (U13.1), [10]USBSPIBridge (U14.22)
FTDI_USB_P: [09]USBHub (U13.2), [10]USBSPIBridge (U14.23)
I2SB_NCE46_CT24_SCCRST_PDMC_TX1_SWO_GP46: [01]MCU (U1.H9), [02]Arduino Headers (P13.13), [03]Breakout Headers (P5.7)
I2SW_NCE28_CT7_M2MOSI_TX0_GP28: [01]MCU (U1.A9), [02]Arduino Headers (P18.4), [10]USBSPIBridge (SB27.2)
M0SCL_M0SCK_RTS0_EXHFA_CT8_GP5: [01]MCU (R4.1), [02]Arduino Headers (P11.11), [03]Breakout Headers (P1.6)
M0SDA_M0MISO_CTS0_CT10_I2SD_GP6: [01]MCU (U1.C9), [02]Arduino Headers (P11.9), [03]Breakout Headers (P1.5)
M1SCL_M1SCK_NCE8_SCCCLK_TX1_GP8: [01]MCU (U1.E10), [02]Arduino Headers (P11.19), [03]Breakout Headers (P1.10)
M1SDA_M1MISO_NCE9_SCCIO_RX1_GP9: [01]MCU (U1.D9), [02]Arduino Headers (P11.17), [03]Breakout Headers (P1.9)
MCU_ADCREF: [01]MCU (C6.2 U1.A6), [02]Arduino Headers (P11.15), [03]Breakout Headers (P1.8)
MSPI1_0_NCE51_CT1_GP51: [01]MCU (U1.B11), [02]Arduino Headers (P11.14), [03]Breakout Headers (P2.7)
MSPI1_1_NCE52_CT2_GP52: [01]MCU (U1.B12), [02]Arduino Headers (P11.12), [03]Breakout Headers (P2.6)
MSPI1_2_NCE53_CT3_GP53: [01]MCU (U1.D10), [02]Arduino Headers (P11.10), [03]Breakout Headers (P2.5)
MSPI1_3_NCE54_CT4_GP54: [01]MCU (U1.C10), [02]Arduino Headers (P11.8), [03]Breakout Headers (P2.4)
MSPI1_4_NCE55_CT5_GP55: [01]MCU (U1.E11), [02]Arduino Headers (P11.6), [03]Breakout Headers (P2.3)
MSPI1_5_NCE56_CT6_GP56: [01]MCU (U1.D11), [02]Arduino Headers (P11.4), [03]Breakout Headers (P2.2)
MSPI1_6_NCE57_CT7_GP57: [01]MCU (U1.C11), [02]Arduino Headers (P11.2), [03]Breakout Headers (P2.1)
MSPI1_7_NCE58_CT8_GP58: [01]MCU (U1.E12), [02]Arduino Headers (P13.16), [03]Breakout Headers (P6.8)
MSPI1_8_NCE59_CT9_GP59: [01]MCU (U1.D12), [02]Arduino Headers (P13.14), [03]Breakout Headers (P6.7)
MSPI1_9_NCE60_CT10_GP60: [01]MCU (U1.C12), [02]Arduino Headers (P13.12), [03]Breakout Headers (P6.6)
MSPI2_0_NCE64_CT14_GP64: [01]MCU (U1.F12), [02]Arduino Headers (P13.4), [03]Breakout Headers (P6.2)
MSPI2_1_NCE65_CT15_GP65: [01]MCU (U1.F11), [02]Arduino Headers (P13.2), [03]Breakout Headers (P6.1)
MSPI2_2_NCE66_CT16_GP66: [01]MCU (U1.G12), [02]Arduino Headers (P17.16), [03]Breakout Headers (P10.8)
MSPI2_3_NCE67_CT17_GP67: [01]MCU (U1.G11), [02]Arduino Headers (P17.14), [03]Breakout Headers (P10.7)
MSPI2_4_NCE68_CT18_GP68: [01]MCU (U1.G10), [02]Arduino Headers (P17.12), [03]Breakout Headers (P10.6)
NCE7_M0MOSI_CKO_TRG0_TX0_CT19_GP7: [01]MCU (U1.C8), [02]Arduino Headers (P11.7), [03]Breakout Headers (P1.4)
NCE41_BLEIRQ_SWO_I2SW_RTS1_TX0_RTS0_GP41: [01]MCU (U1.D7), [02]Arduino Headers (P16.5), [08]Debug Headers and Support (J1.6 U4.3)
RTS0_SCE_NCE3_MSPI7_TRG1_I2SW_GP3: [01]MCU (U1.G3), [02]Arduino Headers (P15.8)
RTS1_NCE44_CT20_M4MOSI_TX0_GP44: [01]MCU (U1.J10), [02]Arduino Headers (P11.1), [03]Breakout Headers (P1.1)
RX0_NCE23_CT14_I2SW_CMP0_MSPI3_EXXT_GP23: [01]MCU (U1.A12), [02]Arduino Headers (P13.1), [03]Breakout Headers (P5.1), [06]J-Link OB Debugger (SB12.2)
RX0_NCE27_CT5_M2SCL_M2SCK_GP27: [01]MCU (U1.B8), [02]Arduino Headers (P17.3), [03]Breakout Headers (P9.2), [10]USBSPIBridge (SB17.2)
RX0_NCE49_CT30_M5SDA_M5MISO_GP49: [01]MCU (U1.H12), [02]Arduino Headers (P13.7), [03]Breakout Headers (P5.4)
RX0_RX1_TRG0_M4SDA_M4MISO_GP40: [01]MCU (U1.J12), [02]Arduino Headers (P17.5), [03]Breakout Headers (P9.3)
RX1_NCE25_CT1_M2SDA_M2MISO_GP25: [01]MCU (U1.A8), [02]Arduino Headers (P17.1), [03]Breakout Headers (P9.1), [10]USBSPIBridge (SB18.2)
RX1_NCE43_CT18_M3SDA_M3MISO_GP43: [01]MCU (U1.J8), [02]Arduino Headers (P11.3), [03]Breakout Headers (P1.2)
RX1_SMISO_RX0_MSPI6_NCE2_GP2: [01]MCU (U1.J4), [02]Arduino Headers (P15.4)
SSCL_SSCK_CKO_MSPI4_NCE0_GP0: [01]MCU (U1.G4), [02]Arduino Headers (P15.3)
SSDA_SMOSI_TX0_MSPI5_NCE1_GP1: [01]MCU (U1.H4), [02]Arduino Headers (P15.1)
SWDCK_NCE20_TX0_TX1_I2SB_RTS1_GP20: [01]MCU (R2.2 U1.F8), [02]Arduino Headers (P16.8), [08]Debug Headers and Support (J1.4 U2.3)
SWDIO_NCE21_RX0_RX1_SCCRST_CTS1_GP21: [01]MCU (R1.2 U1.F7), [02]Arduino Headers (P16.7), [08]Debug Headers and Support (J1.2 U3.3)
SWO_NCE50_CT0_TX0_RX0_TX1_RX1_GP50: [01]MCU (U1.J6), [02]Arduino Headers (P11.16), [03]Breakout Headers (P2.8)
SWO_NCE61_CT11_TX0_RX0_TX1_RX1_GP61: [01]MCU (U1.H6), [02]Arduino Headers (P13.10), [03]Breakout Headers (P6.5)
SWO_NCE62_CT12_CTS0_RTS0_CTS1_RTS1_GP62: [01]MCU (U1.G6), [02]Arduino Headers (P13.8), [03]Breakout Headers (P6.4)
SWO_NCE63_CT13_CTS0_RTS0_CTS1_RTS1_GP63: [01]MCU (U1.H7), [02]Arduino Headers (P13.6), [03]Breakout Headers (P6.3)
SWO_NCE69_CT19_TX0_RX0_TX1_RX1_GP69: [01]MCU (U1.G9), [02]Arduino Headers (P17.10), [03]Breakout Headers (P10.5)
SWO_NCE70_CT20_TX0_RX0_TX1_RX1_GP70: [01]MCU (U1.F9), [02]Arduino Headers (P17.8), [03]Breakout Headers (P10.4)
SWO_NCE71_CT21_TX0_RX0_TX1_RX1_GP71: [01]MCU (U1.J5), [02]Arduino Headers (P17.6), [03]Breakout Headers (P10.3)
SWO_NCE72_CT22_TX0_RX0_TX1_RX1_GP72: [01]MCU (U1.H5), [02]Arduino Headers (P17.4), [03]Breakout Headers (P10.2)
SWO_NCE73_CT23_CTS0_RTS0_CTS1_RTS1_GP73: [01]MCU (U1.G5), [02]Arduino Headers (P17.2), [03]Breakout Headers (P10.1)
TRG1_NCE36_RX1_32K_CTS1_CTS0_PDMD_GP36: [01]MCU (U1.G8), [02]Arduino Headers (P17.13), [03]Breakout Headers (P9.7)
TRG2_NCE37_RTS0_SCCIO_TX1_PDMC_CT29_GP37: [01]MCU (U1.E9), [02]Arduino Headers (P17.11), [03]Breakout Headers (P9.6), [06]J-Link OB Debugger (SB13.2)
TRIG3_NCE38_CTS0_M3MOSI_RX1_GP38: [01]MCU (U1.J7), [02]Arduino Headers (P17.9), [03]Breakout Headers (P9.5), [06]J-Link OB Debugger (SB14.2)
TX0_NCE22_CT12_PDMC_EXLF_MSPI0_SWO_GP22: [01]MCU (U1.B10), [02]Arduino Headers (P13.3), [03]Breakout Headers (P5.2), [06]J-Link OB Debugger (SB11.2)
TX0_NCE48_CT28_M5SCL_M5SCK_GP48: [01]MCU (U1.H11), [02]Arduino Headers (P13.9), [03]Breakout Headers (P5.5)
TX0_TX1_CT25_M4SCL_M4SCK_GP39: [01]MCU (R5.1), [02]Arduino Headers (P17.7), [03]Breakout Headers (P9.4)
TX1_M1MOSI_NCE10_PDMC_RTS1_GP10: [01]MCU (U1.F10), [02]Arduino Headers (P18.2), [07]User Interface (SB23.1)
TX1_NCE24_MSPI8_CTS0_CT21_32K_SWO_GP24: [01]MCU (U1.B9), [02]Arduino Headers (P16.6)
TX1_NCE42_CT16_M3SCL_M3SCK_GP42: [01]MCU (U1.J9), [02]Arduino Headers (P11.5), [03]Breakout Headers (P1.3)
TXEN: [01]MCU (U1.H3), [02]Arduino Headers (P18.3)
USB_N: [04]Power Supplies (D1.2 P23.A7 P23.B7), [09]USBHub (U13.30)
USB_P: [04]Power Supplies (D1.3 P23.A6 P23.B6), [09]USBHub (U13.31)
VDD_EXP: [02]Arduino Headers (5 pins), [03]Breakout Headers (6 pins), [04]Power Supplies (P20.2 SB16.2)
VDD_EXT_DBG: [06]J-Link OB Debugger (SB6.1), [08]Debug Headers and Support (7 pins)
VDD_PS: [04]Power Supplies (6 pins), [06]J-Link OB Debugger (SB5.1)
VIN: [02]Arduino Headers (P12.8), [03]Breakout Headers (P3.8 P4.8)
